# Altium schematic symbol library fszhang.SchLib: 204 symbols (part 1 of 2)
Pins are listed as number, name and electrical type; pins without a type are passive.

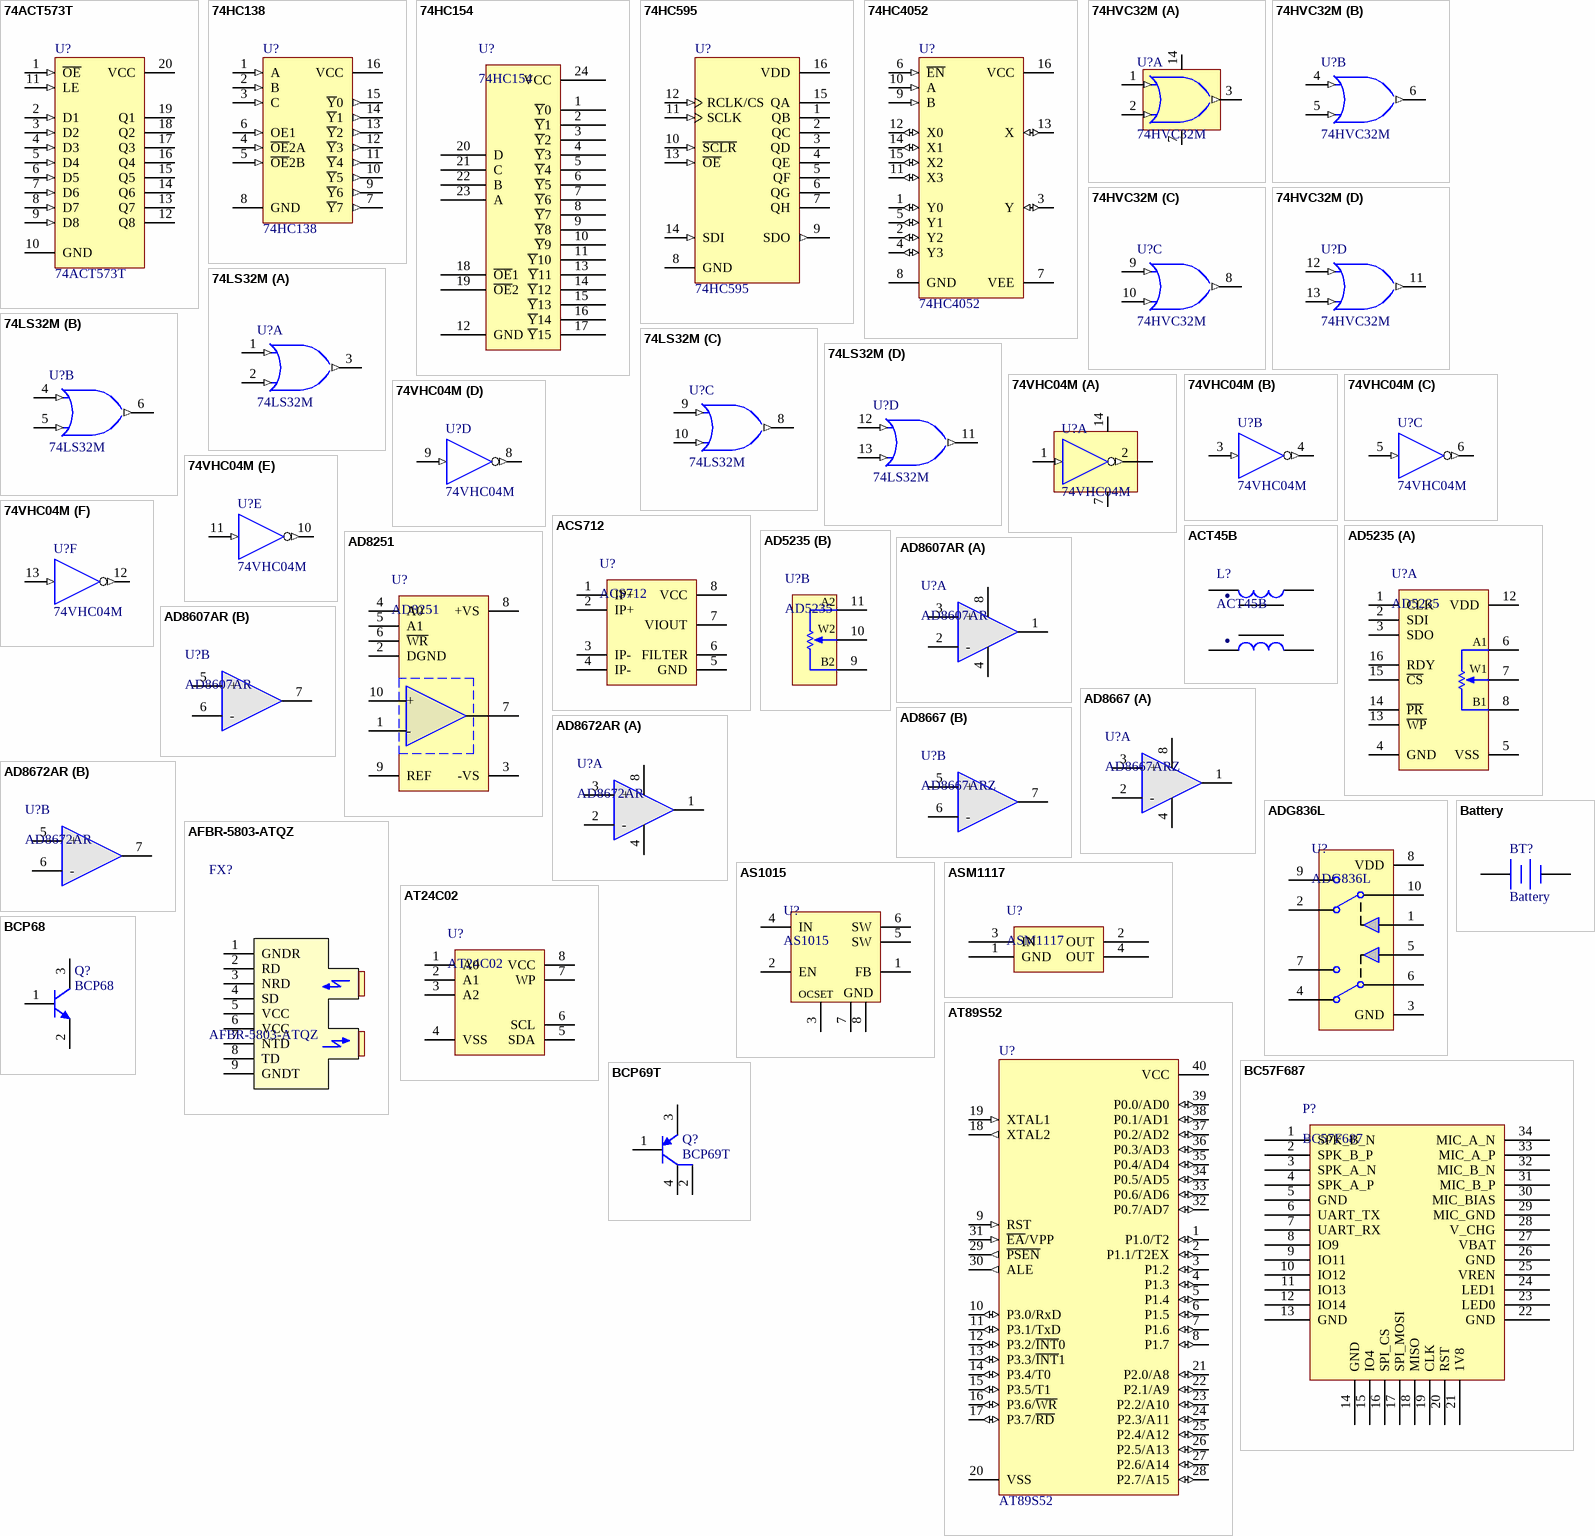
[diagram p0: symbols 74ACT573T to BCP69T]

## 74ACT573T
designator U?
双向数据传输
footprint TSSOP20 (Shrink Small Outline; 20 Leads; Body Width 4.4 mm; Pitch 0.65 mm)
footprint SO20_M (SOIC, 20-Leads, Body 12.8x7.5mm, Pitch 1.27mm, IPC Low Density)
pins: 1 ~{OE} (in), 2 D1 (in), 3 D2 (in), 4 D3 (in), 5 D4 (in), 6 D5 (in), 7 D6 (in), 8 D7 (in), 9 D8 (in), 10 GND (power), 11 LE (in), 12 Q8 (hiz), 13 Q7 (hiz), 14 Q6 (hiz), 15 Q5 (hiz), 16 Q4 (hiz), 17 Q3 (hiz), 18 Q2 (hiz), 19 Q1 (hiz), 20 VCC (power)

## 74HC138
designator U?
138译码器
footprint NSO16_M (SOIC, 16-Leads, Body 9.9x3.9mm, Pitch 1.27mm, IPC Low Density)
footprint DIP16 (8列双排)
pins: 1 A (in), 2 B (in), 3 C (in), 4 ~{OE}2A (in), 5 ~{OE}2B (in), 6 OE1 (in), 7 ~{Y}7 (out), 8 GND (power), 9 ~{Y}6 (out), 10 ~{Y}5 (out), 11 ~{Y}4 (out), 12 ~{Y}3 (out), 13 ~{Y}2 (out), 14 ~{Y}1 (out), 15 ~{Y}0 (out), 16 VCC (power)

## 74HC154
designator U?
4-16译码器
footprint DW024_N (74hc154)
footprint DIP24 (DIP; 24,74ls154)
pins: 1 ~{Y}0 (power), 2 ~{Y}1 (power), 3 ~{Y}2 (power), 4 ~{Y}3 (power), 5 ~{Y}4 (power), 6 ~{Y}5 (power), 7 ~{Y}6 (power), 8 ~{Y}7 (power), 9 ~{Y}8 (power), 10 ~{Y}9 (power), 11 ~{Y}10 (power), 12 GND (power), 13 ~{Y}11 (power), 14 ~{Y}12 (power), 15 ~{Y}13 (power), 16 ~{Y}14 (power), 17 ~{Y}15 (power), 18 ~{OE}1 (power), 19 ~{OE}2 (power), 20 D (power), 21 C (power), 22 B (power), 23 A (power), 24 VCC (power)

## 74HC595
designator U?
移位寄存器; ComponentAvailability: Not for New Design
footprint DIP16 (8列双排)
footprint NSO16_M (SOIC, 16-Leads, Body 9.9x3.9mm, Pitch 1.27mm, IPC Low Density)
pins: 1 QB (hiz), 2 QC (hiz), 3 QD (hiz), 4 QE (hiz), 5 QF (hiz), 6 QG (hiz), 7 QH (hiz), 8 GND (power), 9 SDO (out), 10 ~{SCLR} (in), 11 SCLK (in), 12 RCLK/CS (in), 13 ~{OE} (in), 14 SDI (in), 15 QA (hiz), 16 VDD (power)

## 74HC4052
designator U?
双通道模拟开关
footprint NSO16_M (SOIC, 16-Leads, Body 9.9x3.9mm, Pitch 1.27mm, IPC Low Density)
footprint DIP16
pins: 1 Y0 (io), 2 Y2 (io), 3 Y (io), 4 Y3 (io), 5 Y1 (io), 6 ~{EN} (in), 7 VEE (power), 8 GND (power), 9 B (in), 10 A (in), 11 X3 (io), 12 X0 (io), 13 X (io), 14 X1 (io), 15 X2 (io), 16 VCC (power)

## 74HVC32M
designator U?
双输入或门
footprint SOP-14N (SOP, 14-Leads,)
part A pins: 1 A (in), 2 B (in), 3 Y (out), 7 GND (power), 14 VCC (power)
part B pins: 4 A (in), 5 B (in), 6 Y (out)
part C pins: 8 Y (out), 9 A (in), 10 B (in)
part D pins: 11 Y (out), 12 A (in), 13 B (in)

## 74LS32M
designator U?
双输入或门
footprint SOP-14N (SOP, 14-Leads,)
pins on every part: 7 GND (power) hidden to GND, 14 VCC (power) hidden to VCC
part A pins: 1 A (in), 2 B (in), 3 Y (out)
part B pins: 4 A (in), 5 B (in), 6 Y (out)
part C pins: 8 Y (out), 9 A (in), 10 B (in)
part D pins: 11 Y (out), 12 A (in), 13 B (in)

## 74VHC04M
designator U?
非门; IC_Technology: S
footprint SOP-14N (SOP, 14-Leads,)
part A pins: 1 A (in), 2 Y (out), 7 GND (power), 14 VCC (power)
part B pins: 3 A (in), 4 Y (out)
part C pins: 5 A (in), 6 Y (out)
part D pins: 8 Y (out), 9 A (in)
part E pins: 10 Y (out), 11 A (in)
part F pins: 12 Y (out), 13 A (in)

## ACS712
designator U?
电流检测芯片
footprint SOIC127P610X175-8N (ACS712)
pins: 1 IP+, 2 IP+, 3 IP-, 4 IP-, 5 GND, 6 FILTER, 7 VIOUT, 8 VCC

## ACT45B
designator L?
共模电感
footprint L-TDK
pins: 1, 2, 3, 4

## AD5235
designator U?
数控电阻
footprint TSSOP16_M (TSOP, 16-Leads, Body 5x4.4mm, Pitch 0.65mm, IPC Low Density)
part A pins: 1 CLK, 2 SDI, 3 SDO, 4 GND, 5 VSS, 6 A1, 7 W1, 8 B1, 12 VDD, 13 ~{WP}, 14 ~{PR}, 15 ~{CS}, 16 RDY
part B pins: 9 B2, 10 W2, 11 A2

## AD8251
designator U?
可控增益运放
footprint MSOP-UN10_N (TSSOP)
pins: 1 -, 2 DGND, 3 -VS, 4 A0, 5 A1, 6 ~{WR}, 7 OUT, 8 +VS, 9 REF, 10 +

## AD8607AR
designator U?
双运放
footprint NSO8_N (SOIC-max660)
part A pins: 1 OUT1, 2 -, 3 +, 4 V- (power), 8 V+ (power)
part B pins: 5 +, 6 -, 7 OUT2

## AD8667
designator U?, comment AD8667ARZ
双运放
footprint NSO8_N (SOIC-max660)
part A pins: 1 OUT1, 2 -, 3 +, 4 V- (power), 8 V+ (power)
part B pins: 5 +, 6 -, 7 OUT2

## AD8672AR
designator U?
双运放
footprint NSO8_N (SOIC-max660)
part A pins: 1 OUT1, 2 -, 3 +, 4 V- (power), 8 V+ (power)
part B pins: 5 +, 6 -, 7 OUT2

## ADG836L
designator U?
双刀双掷数字开关
footprint MSOP-UN10_N (TSSOP)
pins: 1 IN1, 2 SA, 3 GND, 4 S2A, 5 IN2, 6 D2, 7 S2B, 8 VDD, 9 S1B, 10 D1

## AFBR-5803-ATQZ
designator FX?
光以太网
footprint AFBR-5803AQZ (光以太网)
pins: 1 GNDR, 2 RD, 3 NRD, 4 SD, 5 VCC, 6 VCC, 7 NTD, 8 TD, 9 GNDT

## AS1015
designator U?
可调升压芯片
footprint NSO8_N (SOIC-max660)
pins: 1 FB (power), 2 EN (power), 3 OCSET (power), 4 IN (power), 5 SW (power), 6 SW (power), 7 GND (power), 8 GND (power)

## ASM1117
designator U?
3.3V稳压芯片
footprint SOT-223 (ASM1117 -3.3V)
pins: 1 GND, 2 OUT, 3 IN, 4 OUT

## AT24C02
designator U?
EEROM存储器
footprint SOIC8_N (8-Pin Small Outline Integrated Circuit Package (SOIC8), IPC Medium Density)
pins: 1 A0, 2 A1, 3 A2, 4 VSS, 5 SDA, 6 SCL, 7 WP, 8 VCC

## AT89S52
designator U?
51系列单片机
footprint DIP-40 (51单片机)
pins: 1 P1.0/T2 (io), 2 P1.1/T2EX (io), 3 P1.2 (io), 4 P1.3 (io), 5 P1.4 (io), 6 P1.5 (io), 7 P1.6 (io), 8 P1.7 (io), 9 RST (in), 10 P3.0/RxD (io), 11 P3.1/TxD (io), 12 P3.2/~{INT}0 (io), 13 P3.3/~{INT}1 (io), 14 P3.4/T0 (io), 15 P3.5/T1 (io), 16 P3.6/~{WR} (io), 17 P3.7/~{RD} (io), 18 XTAL2 (out), 19 XTAL1 (in), 20 VSS (power), 21 P2.0/A8 (io), 22 P2.1/A9 (io), 23 P2.2/A10 (io), 24 P2.3/A11 (io), 25 P2.4/A12 (io), 26 P2.5/A13 (io), 27 P2.6/A14 (io), 28 P2.7/A15 (io), 29 ~{PSEN} (out), 30 ALE (out), 31 ~{EA}/VPP (in), 32 P0.7/AD7 (io), 33 P0.6/AD6 (io), 34 P0.5/AD5 (io), 35 P0.4/AD4 (io), 36 P0.3/AD3 (io), 37 P0.2/AD2 (io), 38 P0.1/AD1 (io), 39 P0.0/AD0 (io), 40 VCC (power)

## Battery
designator BT?
备份电池
footprint CR1220 (钮扣电池)
pins: 1 +, 2 -

## BC57F687
designator P?
蓝牙音频模块
footprint HDR34_BT (蓝牙模块)
pins: 1 SPK_B_N, 2 SPK_B_P, 3 SPK_A_N, 4 SPK_A_P, 5 GND, 6 UART_TX, 7 UART_RX, 8 IO9, 9 IO11, 10 IO12, 11 IO13, 12 IO14, 13 GND, 14 GND, 15 IO4, 16 SPI_CS, 17 SPI_MOSI, 18 MISO, 19 CLK, 20 RST, 21 1V8, 22 GND, 23 LED0, 24 LED1, 25 VREN, 26 GND, 27 VBAT, 28 V_CHG, 29 MIC_GND, 30 MIC_BIAS, 31 MIC_B_P, 32 MIC_B_N, 33 MIC_A_P, 34 MIC_A_N

## BCP68
designator Q?
NPN三极管
footprint SOT-23 (普通?)
pins: 1 B, 2 E, 3 C

## BCP69T
designator Q?
PNP三极管
footprint SOT-223 (ASM1117 -3.3V)
pins: 1 B, 2 C, 3 E, 4

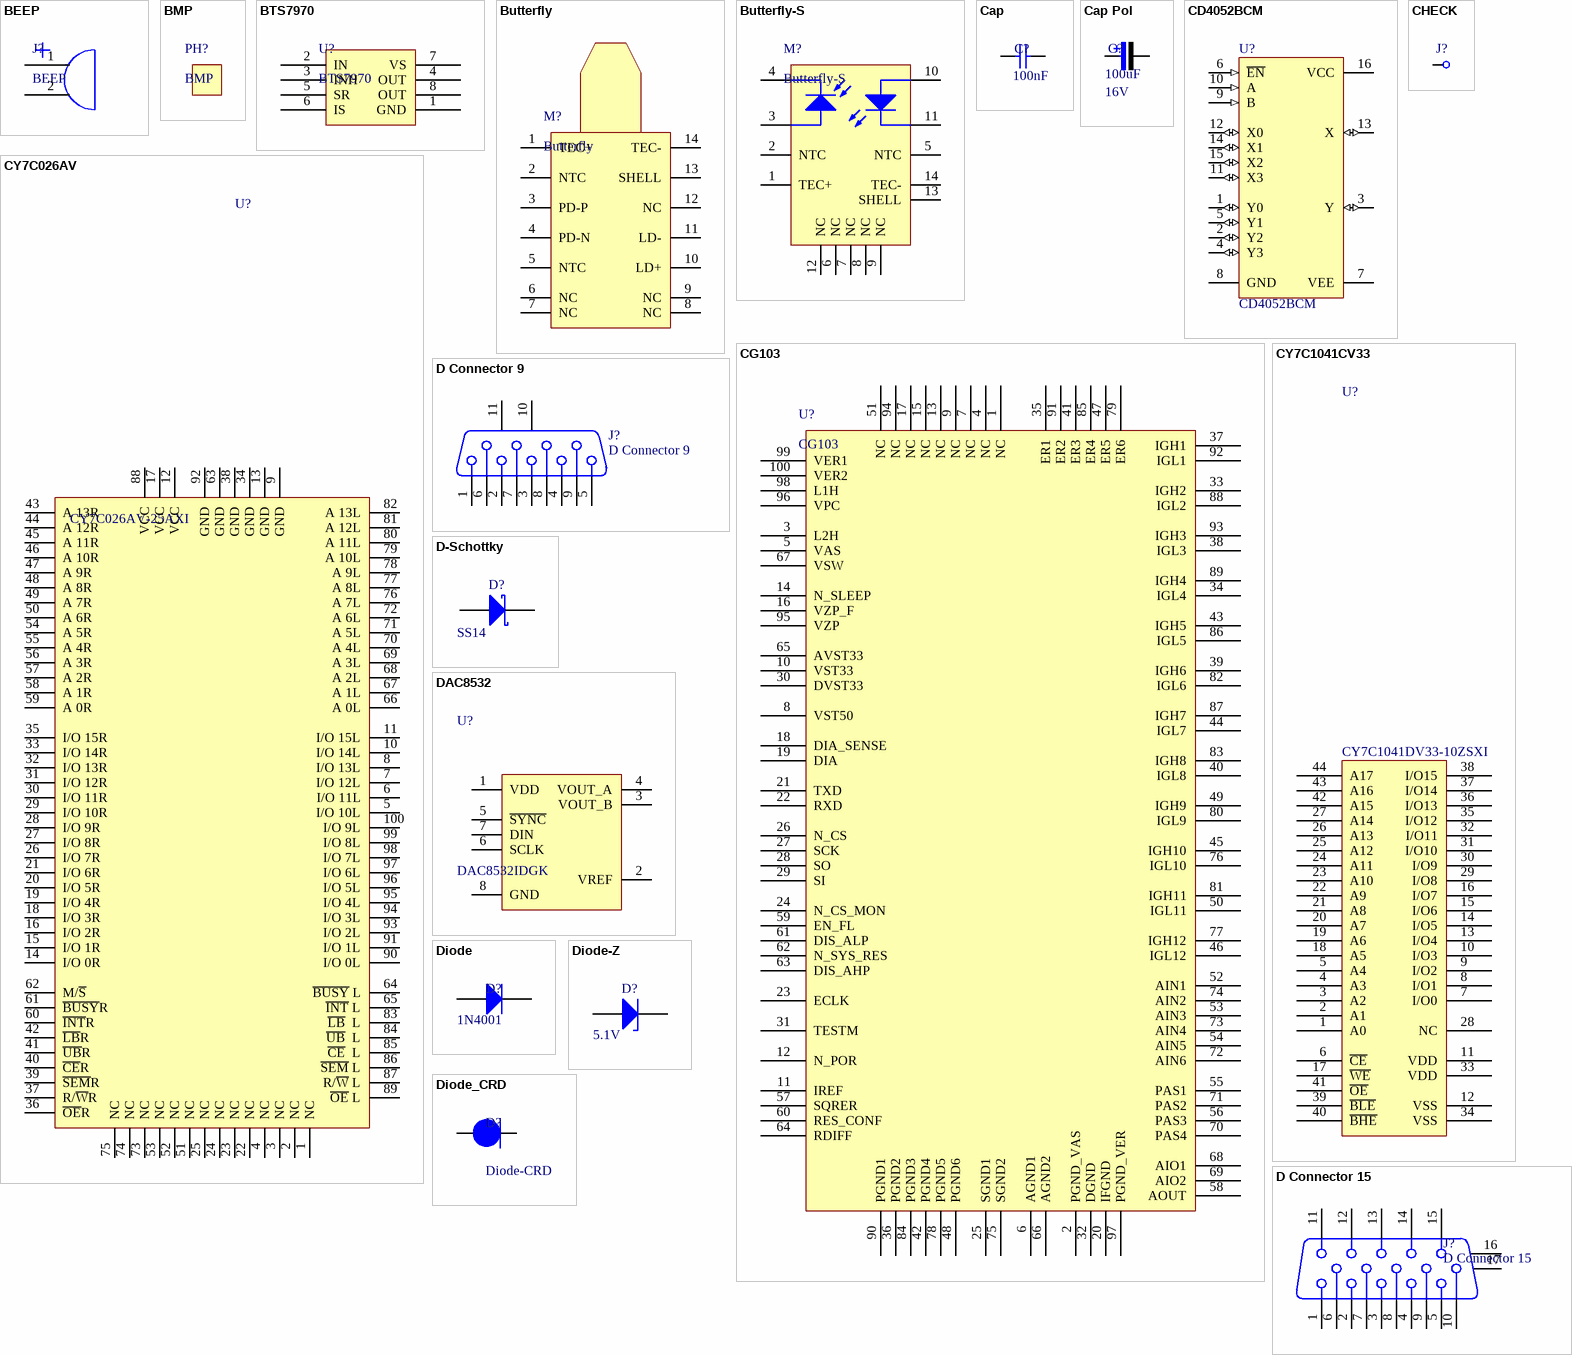
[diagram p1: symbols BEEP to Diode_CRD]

## BEEP
designator J?
蜂鸣器
footprint Beep (蜂鸣器)
pins: 1 0, 2 1

## BMP
designator PH?
闪电符号
footprint LOGO_Thunder
footprint LOGO-3S

## BTS7970
designator U?
电机驱动
footprint TO-263-7 (TO, 8-Pads,7970)
pins: 1 GND (power), 2 IN (power), 3 INH (power), 4 OUT (power), 5 SR (power), 6 IS (power), 7 VS (power), 8 OUT (power)

## Butterfly
designator M?
功率激光器
pins: 1 TEC+, 2 NTC, 3 PD-P, 4 PD-N, 5 NTC, 6 NC, 7 NC, 8 NC, 9 NC, 10 LD+, 11 LD-, 12 NC, 13 SHELL, 14 TEC-

## Butterfly-S
designator M?
功率激光器
pins: 1 TEC+, 2 NTC, 3 PD-P, 4 PD-N, 5 NTC, 6 NC, 7 NC, 8 NC, 9 NC, 10 LD+, 11 LD-, 12 NC, 13 SHELL, 14 TEC-

## Cap
designator C?  value 100nF  (hidden comment: Cap)
无极性电容
footprint C-RAD (瓷片电容)
footprint C-RAD-0805 (贴片电容)
footprint C-RAD-0603 (贴片电容)
footprint 0603-2 (贴片无丝印)
footprint 0805-2 (贴片无丝印)
footprint C-RAD-3528 (贴片电容)
pins: 1, 2

## Cap Pol
designator C?  value 100uF  Vol: 16V  (hidden comment: Cap Pol)
极性电解电容
footprint CAP-7343 (钽电容)
footprint CAP-3528 (钽电容)
footprint CAP-3216 (钽电容)
footprint C-RB-S10 (贴片电解)
footprint C-RB-S6 (贴片电解)
footprint CAP-6032 (钽电容)
footprint C-RB-10 (35V470uF电容)
footprint C-RB-18 (35V2200uF电容)
footprint C-RB-8 (35V 220UF电容)
footprint C-RB-12 (35V470uF电容)
footprint C-RB-S8 (贴片电解)
pins: 1, 2
1 alternate drawing of the same symbol

## CD4052BCM
designator U?
双通道模拟开关
footprint NSO16_M (SOIC, 16-Leads, Body 9.9x3.9mm, Pitch 1.27mm, IPC Low Density)
pins: 1 Y0 (io), 2 Y2 (io), 3 Y (io), 4 Y3 (io), 5 Y1 (io), 6 ~{EN} (in), 7 VEE (power), 8 GND (power), 9 B (in), 10 A (in), 11 X3 (io), 12 X0 (io), 13 X (io), 14 X1 (io), 15 X2 (io), 16 VCC (power)

## CG103
designator U?
BOSCH点火芯片
footprint LQFP-100_M (Thin QFP, 100)
pins: 1 NC, 2 PGND_VAS, 3 L2H, 4 NC, 5 VAS, 6 AGND1, 7 NC, 8 VST50, 9 NC, 10 VST33, 11 IREF, 12 N_POR, 13 NC, 14 N_SLEEP, 15 NC, 16 VZP_F, 17 NC, 18 DIA_SENSE, 19 DIA, 20 IFGND, 21 TXD, 22 RXD, 23 ECLK, 24 N_CS_MON, 25 SGND1, 26 N_CS, 27 SCK, 28 SO, 29 SI, 30 DVST33, 31 TESTM, 32 DGND, 33 IGH2, 34 IGL4, 35 ER1, 36 PGND2, 37 IGH1, 38 IGL3, 39 IGH6, 40 IGL8, 41 ER3, 42 PGND4, 43 IGH5, 44 IGL7, 45 IGH10, 46 IGL12, 47 ER5, 48 PGND6, 49 IGH9, 50 IGL11, 51 NC, 52 AIN1, 53 AIN3, 54 AIN5, 55 PAS1, 56 PAS3, 57 SQRER, 58 AOUT, 59 EN_FL, 60 RES_CONF, 61 DIS_ALP, 62 N_SYS_RES, 63 DIS_AHP, 64 RDIFF, 65 AVST33, 66 AGND2, 67 VSW, 68 AIO1, 69 AIO2, 70 PAS4, 71 PAS2, 72 AIN6, 73 AIN4, 74 AIN2, 75 SGND2, 76 IGL10, 77 IGH12, 78 PGND5, 79 ER6, 80 IGL9, 81 IGH11, 82 IGL6, 83 IGH8, 84 PGND3, 85 ER4, 86 IGL5, 87 IGH7, 88 IGL2, 89 IGH4, 90 PGND1, 91 ER2, 92 IGL1, 93 IGH3, 94 NC, 95 VZP, 96 VPC, 97 PGND_VER, 98 L1H, 99 VER1, 100 VER2

## CHECK
designator J?  (value not drawn)
测试点
footprint CHECK-A (Connector; Plug)
footprint CHECK-B (Connector; Plug)
pins: 1

## CY7C026AV
designator U?, comment CY7C026AV-25AXI
RAM
footprint TQFP100_M (Thin QFP, 100-Leads, Body 14x14mm, Pitch 0.5mm, IPC Low Density)
pins: 1 NC, 2 NC, 3 NC, 4 NC, 5 I/O 10L, 6 I/O 11L, 7 I/O 12L, 8 I/O 13L, 9 GND, 10 I/O 14L, 11 I/O 15L, 12 VCC, 13 GND, 14 I/O 0R, 15 I/O 1R, 16 I/O 2R, 17 VCC, 18 I/O 3R, 19 I/O 4R, 20 I/O 5R, 21 I/O 6R, 22 NC, 23 NC, 24 NC, 25 NC, 26 I/O 7R, 27 I/O 8R, 28 I/O 9R, 29 I/O 10R, 30 I/O 11R, 31 I/O 12R, 32 I/O 13R, 33 I/O 14R, 34 GND, 35 I/O 15R, 36 ~{OE}R, 37 R/~{W}R, 38 GND, 39 ~{SEM}R, 40 ~{CE}R, 41 ~{UB}R, 42 ~{LB}R, 43 A 13R, 44 A 12R, 45 A 11R, 46 A 10R, 47 A 9R, 48 A 8R, 49 A 7R, 50 A 6R, 51 NC, 52 NC, 53 NC, 54 A 5R, 55 A 4R, 56 A 3R, 57 A 2R, 58 A 1R, 59 A 0R, 60 ~{INT}R, 61 ~{BUSY}R, 62 M/~{S}, 63 GND, 64 ~{BUSY} L, 65 ~{INT} L, 66 A 0L, 67 A 1L, 68 A 2L, 69 A 3L, 70 A 4L, 71 A 5L, 72 A 6L, 73 NC, 74 NC, 75 NC, 76 A 7L, 77 A 8L, 78 A 9L, 79 A 10L, 80 A 11L, 81 A 12L, 82 A 13L, 83 ~{LB}  L, 84 ~{UB}  L, 85 ~{CE}  L, 86 ~{SEM} L, 87 R/~{W} L, 88 VCC, 89 ~{OE} L, 90 I/O 0L, 91 I/O 1L, 92 GND, 93 I/O 2L, 94 I/O 3L, 95 I/O 4L, 96 I/O 5L, 97 I/O 6L, 98 I/O 7L, 99 I/O 8L, 100 I/O 9L

## CY7C1041CV33
designator U?, comment CY7C1041DV33-10ZSXI
RAM
footprint TSOP-44N (TSOP, 44-Leads, Body 18.2x10.0mm (max), Pitch 0.80mm, IPC Medium Density)
pins: 1 A0, 2 A1, 3 A2, 4 A3, 5 A4, 6 ~{CE}, 7 I/O0, 8 I/O1, 9 I/O2, 10 I/O3, 11 VDD, 12 VSS, 13 I/O4, 14 I/O5, 15 I/O6, 16 I/O7, 17 ~{WE}, 18 A5, 19 A6, 20 A7, 21 A8, 22 A9, 23 A10, 24 A11, 25 A12, 26 A13, 27 A14, 28 NC, 29 I/O8, 30 I/O9, 31 I/O10, 32 I/O11, 33 VDD, 34 VSS, 35 I/O12, 36 I/O13, 37 I/O14, 38 I/O15, 39 ~{BLE}, 40 ~{BHE}, 41 ~{OE}, 42 A15, 43 A16, 44 A17

## D Connector 9
designator J?
串口; PackageDocument: O; Positions: 9; Gender: Receptacle
footprint DB9-M (DB9公座)
footprint DB9-F (DB9母座)
pins: 1, 2, 3, 4, 5, 6, 7, 8, 9, 10 MH1, 11 MH2

## D Connector 15
designator J?
VGA; PackageDocument: O; Positions: 9; Gender: Receptacle
footprint DB15-M (VGA公)
footprint DB15-F (VGAĸ)
pins: 1, 2, 3, 4, 5, 6, 7, 8, 9, 10, 11, 12, 13, 14, 15, 16 MH2, 17 MH1

## D-Schottky
designator D?  Type: SS14  (hidden comment: D-Schottky)
肖特基二极管
footprint DIODE-SMA (贴片二极管)
footprint DIODE-SMC (SS34贴片肖特基二极管)
footprint DIODE-SMB (DO-214-AA/SMB; 2 C-Bend Leads; Body 5.3 x 3.6 mm, inc. leads (LxW))
pins: 1 A, 2 K

## DAC8532
designator U?, comment DAC8532IDGK
数模转换
footprint TSSOP-8
pins: 1 VDD (power), 2 VREF, 3 VOUT_B, 4 VOUT_A, 5 ~{SYNC}, 6 SCLK, 7 DIN, 8 GND

## Diode
designator D?  Type: 1N4001  (hidden comment: Diode)
二极管
footprint DIODE-AXL (直插二极管)
footprint DIODE-1206 (玻璃封装二极管)
footprint DIODE-SMA (贴片二)
pins: 1 A, 2 K

## Diode-Z
designator D?  value 5.1V  (hidden comment: Diode-Z)
稳压二极管
footprint DIODE-AXL (直插二极管)
footprint DIODE-1206 (玻璃封装二极管)
pins: 1 A, 2 K

## Diode_CRD
designator D?, comment Diode-CRD
恒流二极管
footprint DIODE-AXL (直插二极管)
footprint DIODE-1206 (玻璃封装二极管)
footprint DIODE-SMA (贴片二)
pins: 1 A, 2 K

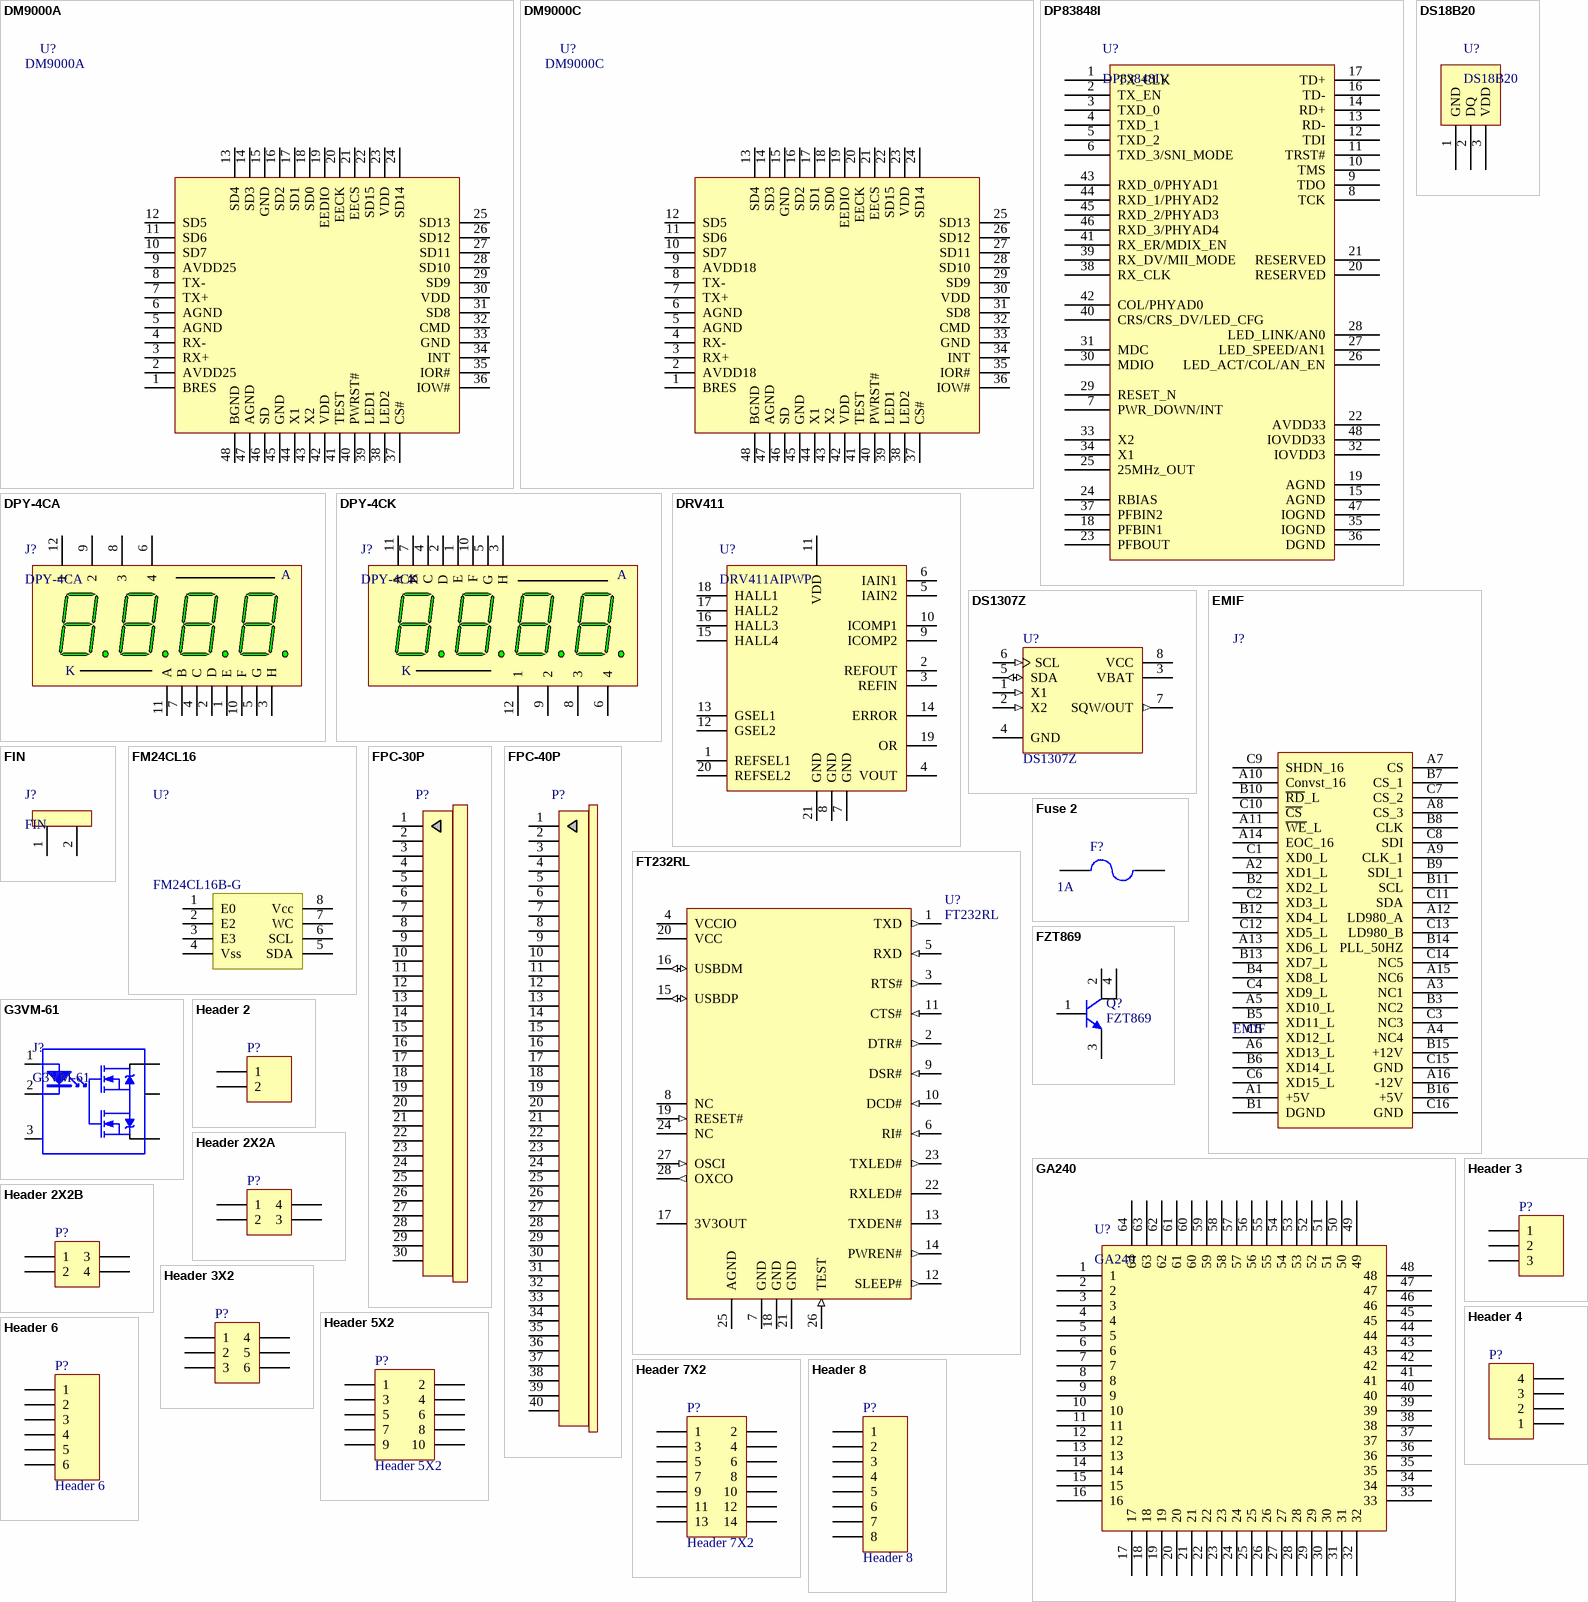
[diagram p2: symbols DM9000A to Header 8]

## DM9000A
designator U?
网络芯片
footprint LQFP-48_M (Thin QFP, 48-Leads, Body 7x7mm, Pitch 0.5mm, IPC Low Density)
pins: 1 BRES, 2 AVDD25, 3 RX+, 4 RX-, 5 AGND, 6 AGND, 7 TX+, 8 TX-, 9 AVDD25, 10 SD7, 11 SD6, 12 SD5, 13 SD4, 14 SD3, 15 GND, 16 SD2, 17 SD1, 18 SD0, 19 EEDIO, 20 EECK, 21 EECS, 22 SD15, 23 VDD, 24 SD14, 25 SD13, 26 SD12, 27 SD11, 28 SD10, 29 SD9, 30 VDD, 31 SD8, 32 CMD, 33 GND, 34 INT, 35 IOR#, 36 IOW#, 37 CS#, 38 LED2, 39 LED1, 40 PWRST#, 41 TEST, 42 VDD, 43 X2, 44 X1, 45 GND, 46 SD, 47 AGND, 48 BGND

## DM9000C
designator U?
网络芯片
footprint LQFP-48_M (Thin QFP, 48-Leads, Body 7x7mm, Pitch 0.5mm, IPC Low Density)
pins: 1 BRES, 2 AVDD18, 3 RX+, 4 RX-, 5 AGND, 6 AGND, 7 TX+, 8 TX-, 9 AVDD18, 10 SD7, 11 SD6, 12 SD5, 13 SD4, 14 SD3, 15 GND, 16 SD2, 17 SD1, 18 SD0, 19 EEDIO, 20 EECK, 21 EECS, 22 SD15, 23 VDD, 24 SD14, 25 SD13, 26 SD12, 27 SD11, 28 SD10, 29 SD9, 30 VDD, 31 SD8, 32 CMD, 33 GND, 34 INT, 35 IOR#, 36 IOW#, 37 CS#, 38 LED2, 39 LED1, 40 PWRST#, 41 TEST, 42 VDD, 43 X2, 44 X1, 45 GND, 46 SD, 47 AGND, 48 BGND

## DP83848I
designator U?, comment DP83848IV
网络芯片
footprint TQFP48_N (Thin QFP, 48-Leads, Body 7x7mm, Pitch 0.5mm, IPC Medium Density)
pins: 1 TX_CLK, 2 TX_EN, 3 TXD_0, 4 TXD_1, 5 TXD_2, 6 TXD_3/SNI_MODE, 7 PWR_DOWN/INT, 8 TCK, 9 TDO, 10 TMS, 11 TRST#, 12 TDI, 13 RD-, 14 RD+, 15 AGND, 16 TD-, 17 TD+, 18 PFBIN1, 19 AGND, 20 RESERVED, 21 RESERVED, 22 AVDD33, 23 PFBOUT, 24 RBIAS, 25 25MHz_OUT, 26 LED_ACT/COL/AN_EN, 27 LED_SPEED/AN1, 28 LED_LINK/AN0, 29 RESET_N, 30 MDIO, 31 MDC, 32 IOVDD3, 33 X2, 34 X1, 35 IOGND, 36 DGND, 37 PFBIN2, 38 RX_CLK, 39 RX_DV/MII_MODE, 40 CRS/CRS_DV/LED_CFG, 41 RX_ER/MDIX_EN, 42 COL/PHYAD0, 43 RXD_0/PHYAD1, 44 RXD_1/PHYAD2, 45 RXD_2/PHYAD3, 46 RXD_3/PHYAD4, 47 IOGND, 48 IOVDD33

## DPY-4CA
designator J?
共阳4位数码管
footprint DYP-4BIT (数码管)
pins: 1 E "Anode", 2 D "Anode", 3 H "Anode", 4 C "Anode", 5 G "Anode", 6 4 "Cathode", 7 B "Anode", 8 3 "Anode", 9 2 "Anode", 10 F "Anode", 11 A "Anode", 12 1 "Cathode"

## DPY-4CK
designator J?
共阴4位数码管
footprint DYP-4BIT (数码管)
pins: 1 E "Anode", 2 D "Anode", 3 H "Anode", 4 C "Anode", 5 G "Anode", 6 4 "Cathode", 7 B "Anode", 8 3 "Anode", 9 2 "Anode", 10 F "Anode", 11 A "Anode", 12 1 "Cathode"

## DRV411
designator U?, comment DRV411AIPWP
闭环磁电流
footprint TSSOP20P_M (TSOP, 20-Leads, Body 6.5x4.4mm, Pitch 0.65mm, IPC Low Density)
pins: 1 REFSEL1, 2 REFOUT, 3 REFIN, 4 VOUT, 5 IAIN2, 6 IAIN1, 7 GND, 8 GND, 9 ICOMP2, 10 ICOMP1, 11 VDD, 12 GSEL2, 13 GSEL1, 14 ERROR, 15 HALL4, 16 HALL3, 17 HALL2, 18 HALL1, 19 OR, 20 REFSEL2, 21 GND

## DS18B20
designator U?
温度传感器
footprint TO-92A (直插三极管)
pins: 1 GND, 2 DQ, 3 VDD

## DS1307Z
designator U?
实时时钟
footprint SOIC8_N (8-Pin Small Outline Integrated Circuit Package (SOIC8), IPC Medium Density)
pins: 1 X1 (in), 2 X2 (in), 3 VBAT (power), 4 GND (power), 5 SDA (io), 6 SCL (in), 7 SQW/OUT (out), 8 VCC (power)

## EMIF
designator J?
接插件
footprint HDR16X3_HA
footprint HDR16X3_HB
pins: A1 +5V, A2 XD1_L, A3 NC1, A4 NC4, A5 XD10_L, A6 XD13_L, A7 CS, A8 CS_3, A9 CLK_1, A10 Convst_16, A11 ~{WE}_L, A12 LD980_A, A13 XD6_L, A14 EOC_16, A15 NC6, A16 -12V, B1 DGND, B2 XD2_L, B3 NC2, B4 XD8_L, B5 XD11_L, B6 XD14_L, B7 CS_1, B8 CLK, B9 SDI_1, B10 ~{RD}_L, B11 SCL, B12 XD4_L, B13 XD7_L, B14 PLL_50HZ, B15 +12V, B16 +5V, C1 XD0_L, C2 XD3_L, C3 NC3, C4 XD9_L, C5 XD12_L, C6 XD15_L, C7 CS_2, C8 SDI, C9 SHDN_16, C10 ~{CS}, C11 SDA, C12 XD5_L, C13 LD980_B, C14 NC5, C15 GND, C16 GND

## FIN
designator J?
散热片
footprint FIN-P2
pins: 1, 2

## FM24CL16
designator U?, comment FM24CL16B-G
铁电存储器
footprint NSO8_N (SOIC-max660)
pins: 1 E0, 2 E2, 3 E3, 4 Vss, 5 SDA, 6 SCL, 7 WC, 8 Vcc

## FPC-30P
designator P?, comment FPC  (value not drawn)
FPC排线连接器
footprint FPC0.8-30P-A (FPC)
pins: 1, 2, 3, 4, 5, 6, 7, 8, 9, 10, 11, 12, 13, 14, 15, 16, 17, 18, 19, 20, 21, 22, 23, 24, 25, 26, 27, 28, 29, 30

## FPC-40P
designator P?, comment FPC  (value not drawn)
FPC排线连接器
footprint FPC0.5-40P-A
pins: 1, 2, 3, 4, 5, 6, 7, 8, 9, 10, 11, 12, 13, 14, 15, 16, 17, 18, 19, 20, 21, 22, 23, 24, 25, 26, 27, 28, 29, 30, 31, 32, 33, 34, 35, 36, 37, 38, 39, 40

## FT232RL
designator U?
USB转串口
footprint SSOP-28 (FT232)
pins: 1 TXD (out), 2 DTR# (out), 3 RTS# (out), 4 VCCIO (power), 5 RXD (in), 6 RI# (in), 7 GND (power), 8 NC, 9 DSR# (in), 10 DCD# (in), 11 CTS# (in), 12 SLEEP# (out), 13 TXDEN# (oc), 14 PWREN# (out), 15 USBDP (io), 16 USBDM (io), 17 3V3OUT (power), 18 GND (power), 19 RESET# (in), 20 VCC (power), 21 GND (power), 22 RXLED# (oc), 23 TXLED# (out), 24 NC, 25 AGND (power), 26 TEST (in), 27 OSCI (in), 28 OXCO (out)

## Fuse 2
designator F?, comment value 1A  (hidden comment: Fuse)
保险丝
footprint 1812 (3.5A保险丝)
pins: 1, 2

## FZT869
designator Q?
NPN三极管
footprint SOT-223 (ASM1117 -3.3V)
pins: 1 B, 2 C, 3 E, 4 C

## G3VM-61
designator J?
半导体继电器
footprint SOT254P-6 (继电器)
pins: 1 A "Anode", 2 K "Cathode", 3, 4, 5, 6

## GA240
designator U?
Freescale16位单片机
footprint LQFP-64 (LQFP64)
pins: 1, 2, 3, 4, 5, 6, 7, 8, 9, 10, 11, 12, 13, 14, 15, 16, 17, 18, 19, 20, 21, 22, 23, 24, 25, 26, 27, 28, 29, 30, 31, 32, 33, 34, 35, 36, 37, 38, 39, 40, 41, 42, 43, 44, 45, 46, 47, 48, 49, 50, 51, 52, 53, 54, 55, 56, 57, 58, 59, 60, 61, 62, 63, 64

## Header 2
designator P?  (value not drawn)
接插件
footprint HDR2X1_C (3.81接插件)
footprint HDR2X1_D1 (5.08mm端)
footprint HDR2X1_A (Connector; Header; 2 Position)
footprint HDR2X1_B2 (Connector; Header; 4 Position)
footprint HDR2X1_B1 (Connector; Header; 4 Position)
footprint HDR2X1_D2 (Connector; Header; 4 Position)
pins: 1, 2

## Header 2X2A
designator P?  (value not drawn)
接插件
footprint HDR2X2_A (Connector; Header; 2 Position)
pins: 1, 2, 3, 4

## Header 2X2B
designator P?  (value not drawn)
接插件
footprint HDR2X2_B (Connector; Header; 2 Position)
pins: 1, 2, 3, 4

## Header 3
designator P?  (value not drawn)
接插件
footprint HDR3X1_B1 (Connector; Header; 3 Position)
footprint HDR3X1_A (Connector; Header; 3 Position)
footprint HDR3X1_C (3.81MM接插件)
footprint HDR3X1_D1 (5.08mm端子)
footprint HDR3X1_D2 (5.08mm端子)
footprint HDR3X1_B2 (Connector; Header; 3 Position)
footprint HDR3X1_B4 (Connector; Header; 4 Position)
pins: 1, 2, 3

## Header 3X2
designator P?  (value not drawn)
接插件
footprint HDR3X2_A2_2.0
pins: 1, 2, 3, 4, 5, 6

## Header 4
designator P?  (value not drawn)
接插件
footprint HDR4X1_A (Connector; Header; 4 Position)
footprint HDR4X1_B1 (Connector; Header; 4 Position)
footprint HDR4X1_B2 (Connector; Header; 4 Position)
footprint HDR4X1_F
footprint HDR4X1_C (3.81MM接插件)
pins: 1, 2, 3, 4

## Header 5X2
designator P?
接插件
footprint HDR5X2_A3
footprint HDR5X2_A1 (Connector; Header; 5x2 Position)
footprint HDR5X2_B1_2.0
footprint HDR5X2_C2
pins: 1, 2, 3, 4, 5, 6, 7, 8, 9, 10

## Header 6
designator P?
接插件
footprint HDR6X1_B2 (Connector; Header; 3 Position)
footprint HDR6X1_B1 (Connector; Header; 4 Position)
footprint HDR6X1_A (Connector; Header; 4 Position)
pins: 1, 2, 3, 4, 5, 6

## Header 7X2
designator P?
Header, 7-Pin
footprint HDR7X2_A1 (Connector; Header; 7x2 Position)
footprint HDR7X2_B1 (Connector)
footprint HDR7X2_B1_2.0
pins: 1, 2, 3, 4, 5, 6, 7, 8, 9, 10, 11, 12, 13, 14

## Header 8
designator P?
Header, 8-Pin
footprint PH2.0-8P
pins: 1, 2, 3, 4, 5, 6, 7, 8

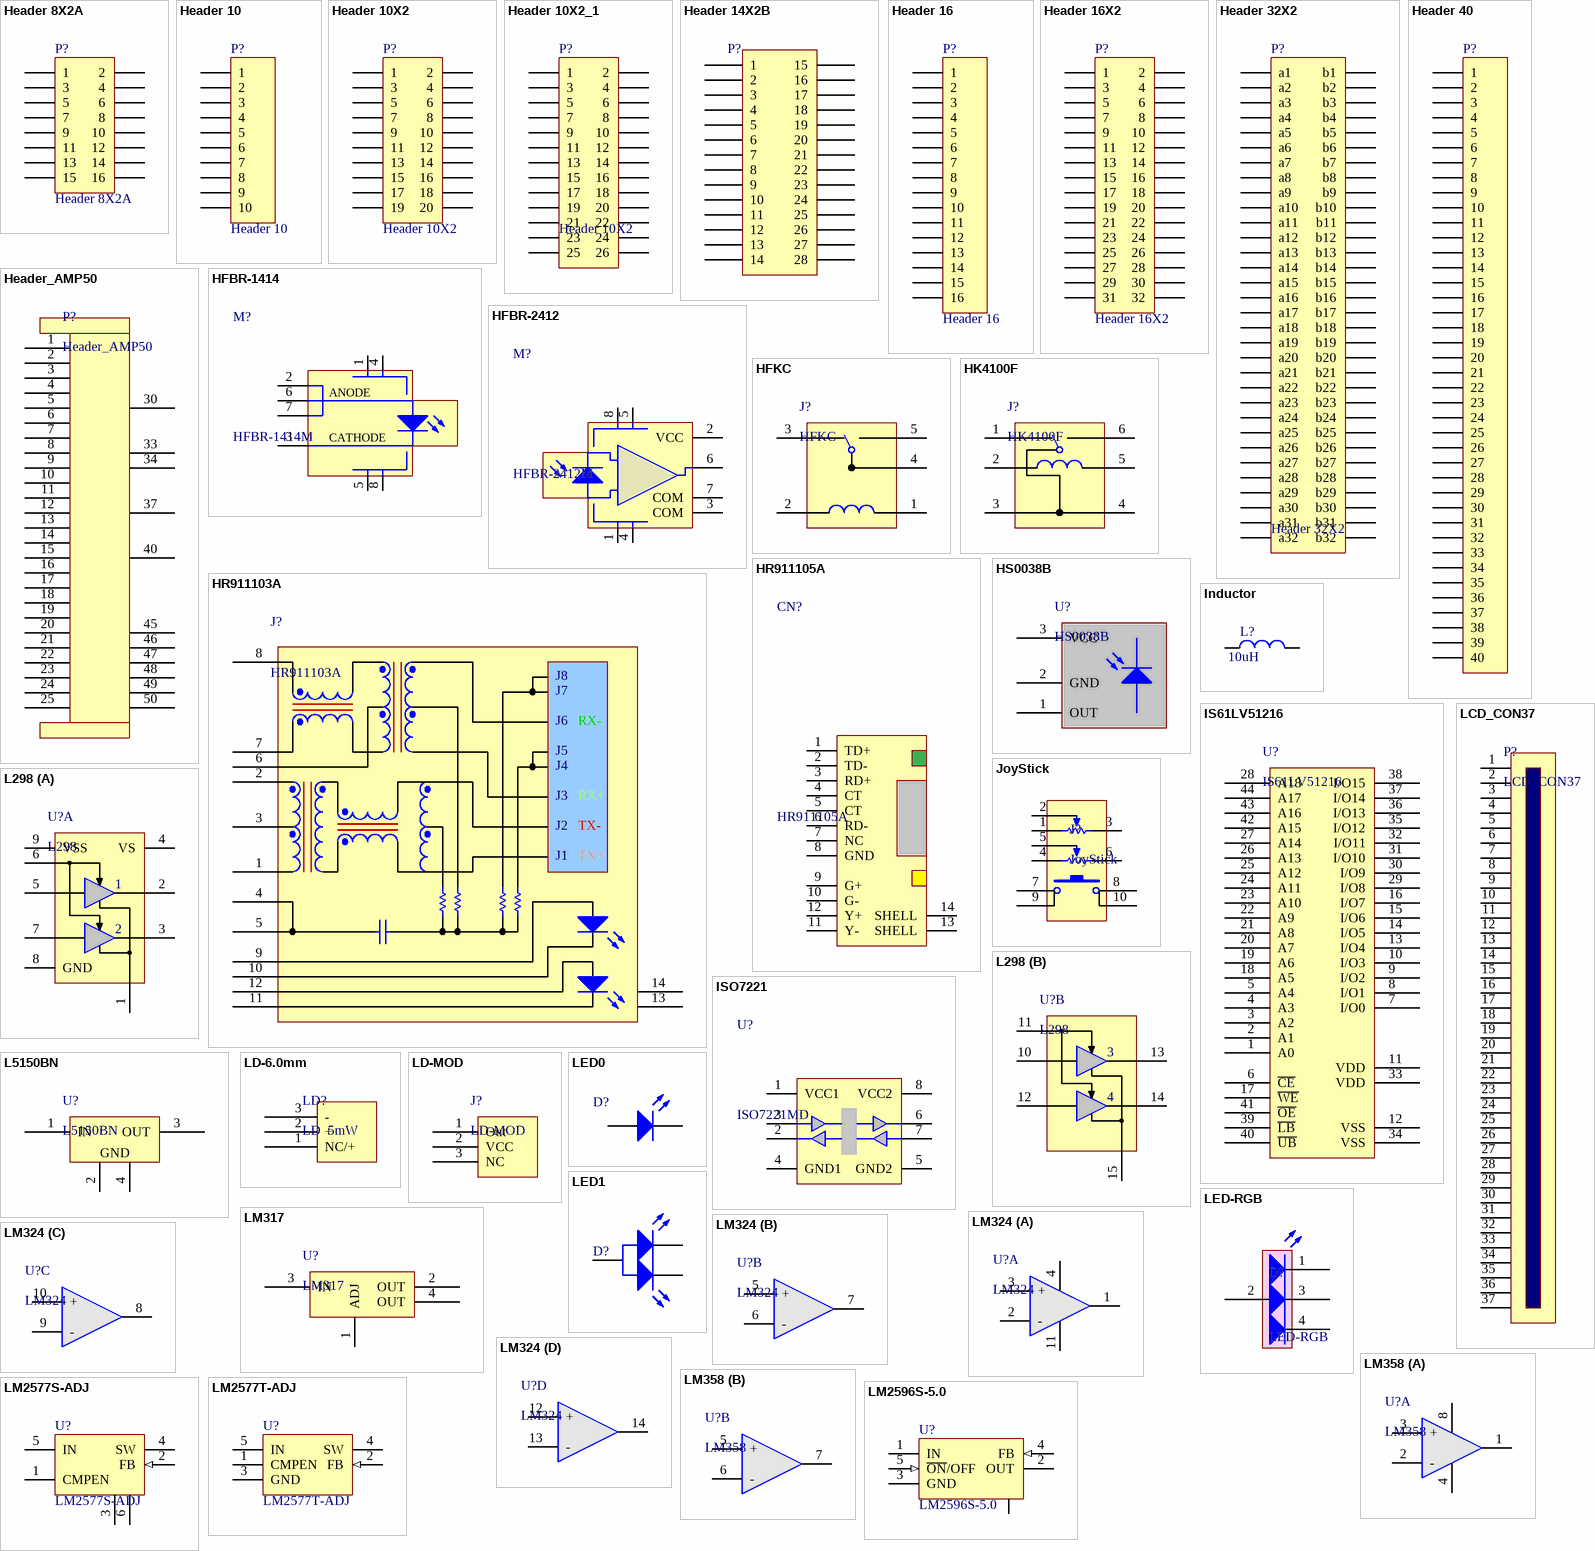
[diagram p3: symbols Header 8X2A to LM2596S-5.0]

## Header 8X2A
designator P?
接插件
footprint HDR8X2_A1 (Connector; Header; 8x2 Position)
footprint HDR8X2_E1
pins: 1, 2, 3, 4, 5, 6, 7, 8, 9, 10, 11, 12, 13, 14, 15, 16

## Header 10
designator P?
Header, 10-Pin
footprint PH2.0-10P
pins: 1, 2, 3, 4, 5, 6, 7, 8, 9, 10

## Header 10X2
designator P?
Header, 10-Pin
footprint HDR10X2_A1 (Connector; Header; 10x2 Position)
footprint HDR10X2_B1
footprint HDR10X2_B1_2.0
pins: 1, 2, 3, 4, 5, 6, 7, 8, 9, 10, 11, 12, 13, 14, 15, 16, 17, 18, 19, 20

## Header 10X2_1
designator P?, comment Header 10X2
Header, 10-Pin
pins: 1, 2, 3, 4, 5, 6, 7, 8, 9, 10, 11, 12, 13, 14, 15, 16, 17, 18, 19, 20, 21, 22, 23, 24, 25, 26

## Header 14X2B
designator P?  (value not drawn)
2*14双排插针
footprint HDR14X2_A2
pins: 1 (power), 2 (power), 3 (power), 4 (power), 5 (power), 6 (power), 7 (power), 8 (power), 9 (power), 10 (power), 11 (power), 12 (power), 13 (power), 14 (power), 15 (power), 16 (power), 17 (power), 18 (power), 19 (power), 20 (power), 21 (power), 22 (power), 23 (power), 24 (power), 25 (power), 26 (power), 27 (power), 28 (power)

## Header 16
designator P?
Header16贴片
footprint HDR16X1_A (Connector; Header; 16 Position)
footprint FPC1.0-16P-A (FPC)
pins: 1, 2, 3, 4, 5, 6, 7, 8, 9, 10, 11, 12, 13, 14, 15, 16

## Header 16X2
designator P?
接插件
footprint HDR16X2 (Connector; Header; 16x2 Position)
footprint HDR16X2-HB
pins: 1, 2, 3, 4, 5, 6, 7, 8, 9, 10, 11, 12, 13, 14, 15, 16, 17, 18, 19, 20, 21, 22, 23, 24, 25, 26, 27, 28, 29, 30, 31, 32

## Header 32X2
designator P?
接插件
footprint HDR32X2_HA (Connector; Header; 30x2 Position)
footprint HDR32X2_HB (Connector; Header; 30x2 Position)
pins: a1, a2, a3, a4, a5, a6, a7, a8, a9, a10, a11, a12, a13, a14, a15, a16, a17, a18, a19, a20, a21, a22, a23, a24, a25, a26, a27, a28, a29, a30, a31, a32, b1, b2, b3, b4, b5, b6, b7, b8, b9, b10, b11, b12, b13, b14, b15, b16, b17, b18, b19, b20, b21, b22, b23, b24, b25, b26, b27, b28, b29, b30, b31, b32

## Header 40
designator P?  (value not drawn)
接插件
footprint HDR40X1_A (Connector; Header; 30 Position)
pins: 1, 2, 3, 4, 5, 6, 7, 8, 9, 10, 11, 12, 13, 14, 15, 16, 17, 18, 19, 20, 21, 22, 23, 24, 25, 26, 27, 28, 29, 30, 31, 32, 33, 34, 35, 36, 37, 38, 39, 40

## Header_AMP50
designator P?
控制器接插件
footprint HDR25X2_H (控制器接插件)
pins: 1, 2, 3, 4, 5, 6, 7, 8, 9, 10, 11, 12, 13, 14, 15, 16, 17, 18, 19, 20, 21, 22, 23, 24, 25, 30, 33, 34, 37, 40, 45, 46, 47, 48, 49, 50

## HFBR-1414
designator M?, comment HFBR-1414M
光发送
footprint HFBR-X41XMZ
pins: 1 NC, 2 ANODE, 3 CATHODE, 4 NC, 5 NC, 6 ANODE, 7 ANODE, 8 NC

## HFBR-2412
designator M?, comment HFBR-2412M
光接收
footprint HFBR-X41XMZ
pins: 1 NC, 2 VCC, 3 COM, 4 NC, 5 NC, 6 DATA, 7 COM, 8 NC

## HFKC
designator J?
单刀双掷继电器
footprint HFKC (继电器)
pins: 1, 2, 3, 4, 5

## HK4100F
designator J?
单刀双掷继电器
footprint HK4100F (继电器)
pins: 1, 2, 3, 4, 5, 6

## HR911103A
designator J?
网络接口; PackageDocument: 1988
footprint RJ8-HR911103A (网线接口)
pins: 1 TD+, 2 TD-, 3 TD-, 4 TD-, 5 GND, 6 GND, 7 RD+, 8 RD-, 9 GLED+, 10 GLED-, 11 YLED-, 12 YLED+, 13, 14

## HR911105A
designator CN?
以太网接口
footprint RJ8-HR911105B
footprint RJ8-HR911105A
pins: 1 TD+, 2 TD-, 3 RD+, 4 CT, 5 CT, 6 RD-, 7 NC, 8 GND, 9 G+, 10 G-, 11 Y-, 12 Y+, 13 SHELL, 14 SHELL

## HS0038B
designator U?
红外接收器
footprint HS0038B (红外接收头)
pins: 1 OUT, 2 GND, 3 VCC

## Inductor
designator L?  value 10uH  (hidden comment: Inductor)
电感; Code_IEC: 1005
footprint L-SMD-7 (贴片电感7*7)
footprint L-RB-8 (Inductor)
footprint 1206 (10UH贴片电感)
footprint 0805-1 (贴片带丝印)
footprint L-RB-8F (ֱ?)
footprint L-SMD-10 (贴片电感10*10)
footprint L-SMD-12 (贴片电感12*12)
footprint 0805-2 (贴片无丝印)
pins: 1, 2

## IS61LV51216
designator U?
静态RAM
footprint TSOP-44N (TSOP, 44-Leads, Body 18.2x10.0mm (max), Pitch 0.80mm, IPC Medium Density)
pins: 1 A0, 2 A1, 3 A2, 4 A3, 5 A4, 6 ~{CE}, 7 I/O0, 8 I/O1, 9 I/O2, 10 I/O3, 11 VDD, 12 VSS, 13 I/O4, 14 I/O5, 15 I/O6, 16 I/O7, 17 ~{WE}, 18 A5, 19 A6, 20 A7, 21 A8, 22 A9, 23 A10, 24 A11, 25 A12, 26 A13, 27 A14, 28 A18, 29 I/O8, 30 I/O9, 31 I/O10, 32 I/O11, 33 VDD, 34 VSS, 35 I/O12, 36 I/O13, 37 I/O14, 38 I/O15, 39 ~{LB}, 40 ~{UB}, 41 ~{OE}, 42 A15, 43 A16, 44 A17

## ISO7221
designator U?, comment ISO7221MD
隔离芯片
footprint NSO8_N (SOIC-max660)
pins: 1 VCC1, 2 OutA, 3 B, 4 GND1, 5 GND2, 6 OutB, 7 InA, 8 VCC2

## JoyStick
designator J?
模拟摇杆
footprint JoyStick (模拟摇杆)
pins: 1 BOT, 2 TAP, 3 TOP, 4 BOT, 5 TAP, 6 TOP, 7, 8, 9, 10

## L298
designator U?
ST双电桥
footprint Multiwatt15-V
part A pins: 1 SENSEA, 2 OUT1, 3 OUT2, 4 VS, 5 IN1, 6 ENA, 7 IN2, 8 GND, 9 VSS
part B pins: 10 IN3, 11 ENB, 12 IN4, 13 OUT3, 14 OUT4, 15 SENSEB

## L5150BN
designator U?
5V稳压芯片
footprint SOT-223 (ASM1117 -3.3V)
pins: 1 IN, 2 GND, 3 OUT, 4 GND

## LCD_CON37
designator P?
LCD接口
footprint HDR37X1_F
pins: 1, 2, 3, 4, 5, 6, 7, 8, 9, 10, 11, 12, 13, 14, 15, 16, 17, 18, 19, 20, 21, 22, 23, 24, 25, 26, 27, 28, 29, 30, 31, 32, 33, 34, 35, 36, 37

## LD-6.0mm
designator LD?, comment LD  5mW
5MW激光
footprint LD-6.0 (激光直径6.0mm)
pins: 1 NC/+ (power), 2 + (power), 3 - (power)

## LD-MOD
designator J?
激光调制管
footprint LD-MOD (激光调制管)
pins: 1 Out (power), 2 VCC (power), 3 NC (power)

## LED0
designator D?  (value not drawn)
发光二极管
footprint LED_A1 (直径3MM发?)
footprint LED_0805 (贴片二?)
footprint LED_A2 (直径3MM?)
footprint LED-3528 (贴片二极管)
footprint LED_0603 (贴片无丝印)
pins: 1 A, 2 K

## LED1
designator D?  (value not drawn)
˫ɫLED
footprint LED_A3 (直径3MM二极管)
pins: 1 K1, 2 A, 3 K2

## LED-RGB
designator D?
三基色LED
footprint LED-RGB
pins: 1 R, 2 A, 3 G, 4 B

## LM317
designator U?
稳压芯片
footprint SOT-223 (ASM1117 -3.3V)
pins: 1 ADJ, 2 OUT, 3 IN, 4 OUT

## LM324
designator U?
4运放SOP8芯片
footprint SOP-14N (SOP, 14-Leads,)
part A pins: 1 OUT, 2 -, 3 +, 4 V+, 11 V-
part B pins: 5 +, 6 -, 7 OUT
part C pins: 8 OUT, 9 -, 10 +
part D pins: 12 +, 13 -, 14 OUT

## LM358
designator U?
双运放
footprint NSO8_N (SOIC-max660)
part A pins: 1 OUT1, 2 -, 3 +, 4 V- (power), 8 V+ (power)
part B pins: 5 +, 6 -, 7 OUT2

## LM2577S-ADJ
designator U?
DC升压; Note: Tab is connected to GND
footprint TO-263-5 (贴片LM2596)
pins: 1 CMPEN, 2 FB (in), 3 GND (power), 4 SW (power), 5 IN (power), 6

## LM2577T-ADJ
designator U?
DC升压; Note: Tab is connected to GND
footprint T05A (TO, Thru-Hole, Vertical, Heatsink Mounted; 5 In-Line Leads; Pitch 1.70 mm)
footprint T05D
pins: 1 CMPEN, 2 FB (in), 3 GND (power), 4 SW (power), 5 IN (power)

## LM2596S-5.0
designator U?
5V稳压芯片; Note: Tab is connected to GND
footprint TO-263-5 (贴片LM2596)
pins: 1 IN (power), 2 OUT (power), 3 GND (power), 4 FB (in), 5 ~{ON}/OFF (in), 6 (power)

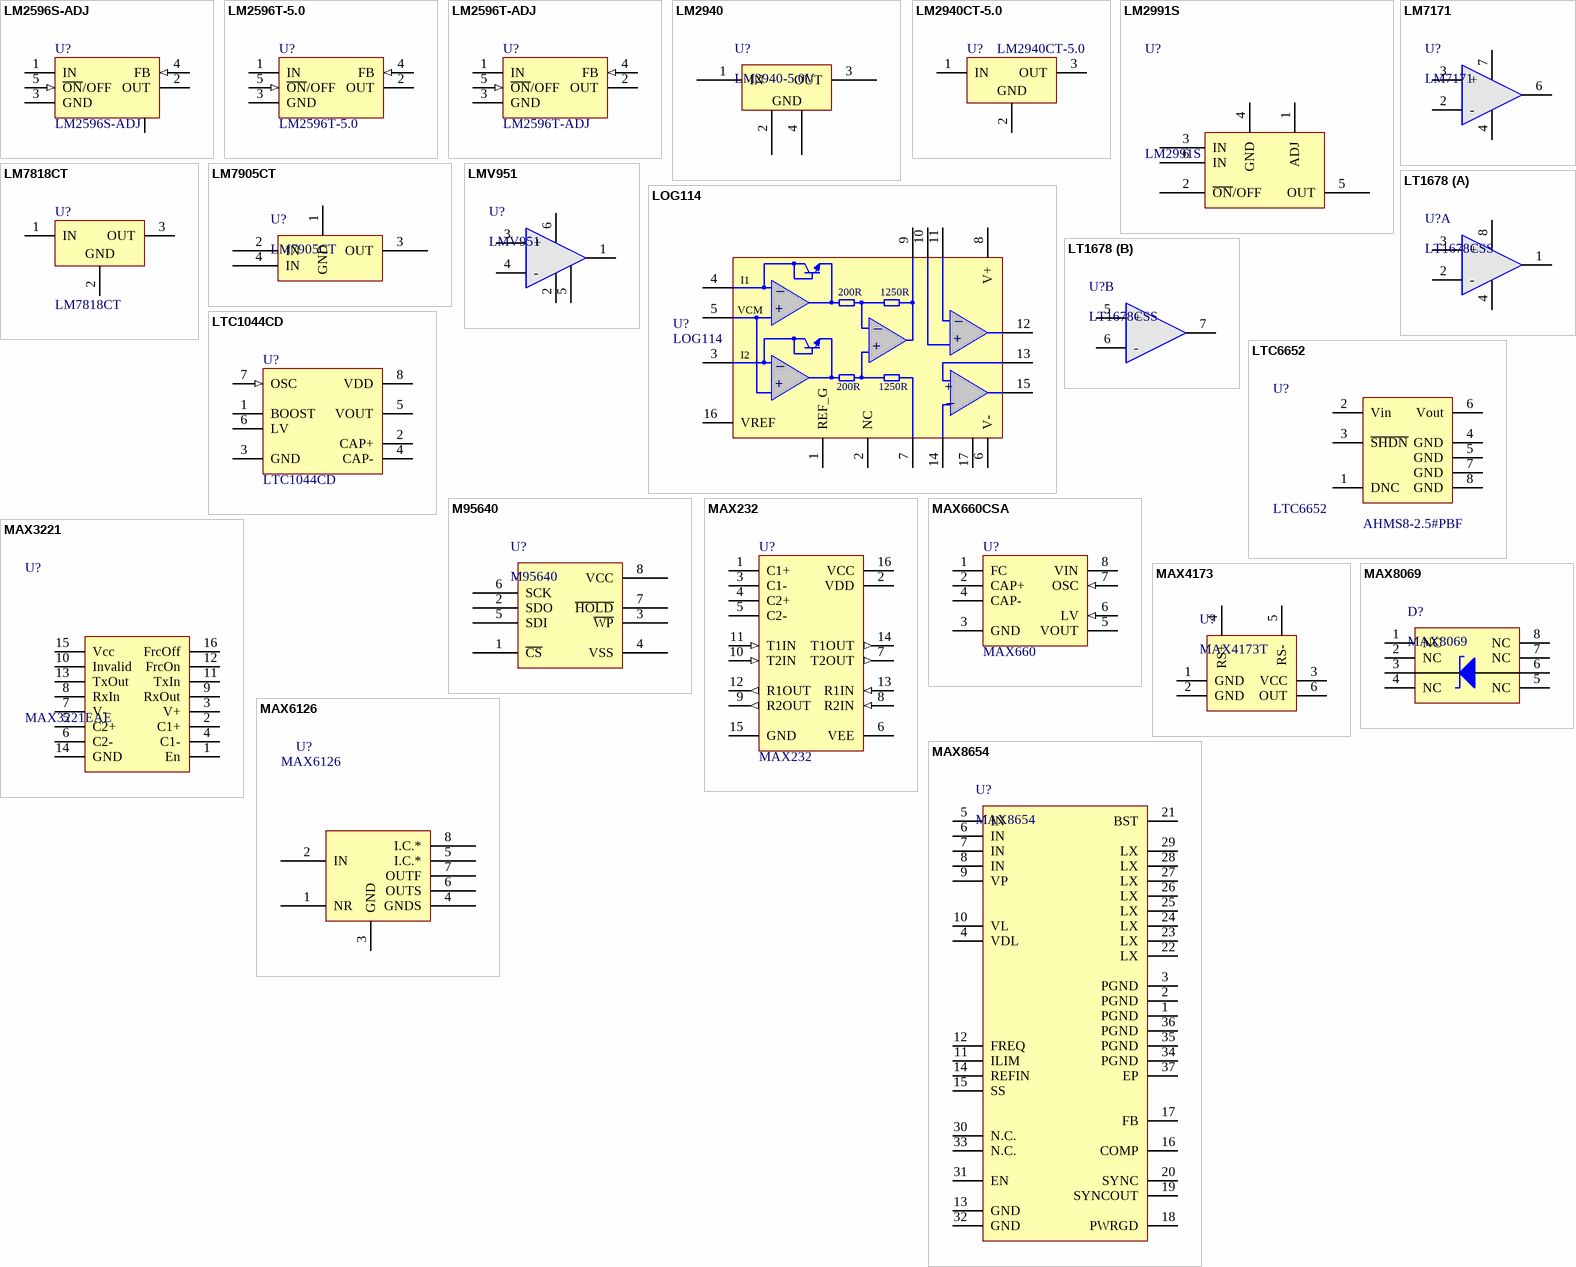
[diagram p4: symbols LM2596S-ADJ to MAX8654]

## LM2596S-ADJ
designator U?
可调稳压芯片; Note: Tab is connected to GND
footprint TO-263-5 (贴片LM2596)
pins: 1 IN (power), 2 OUT (power), 3 GND (power), 4 FB (in), 5 ~{ON}/OFF (in), 6 (power)

## LM2596T-5.0
designator U?
5V稳压芯片; Note: Tab is connected to GND
footprint T05A (TO, Thru-Hole, Vertical, Heatsink Mounted; 5 In-Line Leads; Pitch 1.70 mm)
footprint T05D
pins: 1 IN (power), 2 OUT (power), 3 GND (power), 4 FB (in), 5 ~{ON}/OFF (in)

## LM2596T-ADJ
designator U?
可调稳压芯片; Note: Tab is connected to GND
footprint T05A (TO, Thru-Hole, Vertical, Heatsink Mounted; 5 In-Line Leads; Pitch 1.70 mm)
footprint T05D
pins: 1 IN (power), 2 OUT (power), 3 GND (power), 4 FB (in), 5 ~{ON}/OFF (in)

## LM2940
designator U?, comment LM2940-5.0V
5V稳压芯片
footprint TO-263-3 (LM2940/LM1086)
pins: 1 IN (power), 2 GND (power), 3 OUT (power), 4 GND (power)

## LM2940CT-5.0
designator U?
1A 5V; Note: Tab is connected to GND
footprint T03B (TO, Thru-Hole, Vertical, Heatsink Mounted; 3 In-Line Leads; Pitch 2.54 mm)
pins: 1 IN (power), 2 GND (power), 3 OUT (power)

## LM2991S
designator U?
稳压芯片
footprint TO-263-5 (贴片LM2596)
pins: 1 ADJ, 2 ~{ON}/OFF, 3 IN, 4 GND, 5 OUT, 6 IN

## LM7171
designator U?
单运放
footprint NSO8_N (SOIC-max660)
pins: 2 -, 3 +, 4 V- (power), 6 OUT1, 7 V+ (power)

## LM7818CT
designator U?
Series 3-Terminal Positive Regulator; Note: Tab is connected to GND; ComponentAvailability: Obsolete
footprint T03B (TO, Thru-Hole, Vertical, Heatsink Mounted; 3 In-Line Leads; Pitch 2.54 mm)
pins: 1 IN (power), 2 GND (power), 3 OUT (power)

## LM7905CT
designator U?
稳压芯片
footprint SOT-223 (ASM1117 -3.3V)
footprint TO-263-3 (LM2940/LM1086)
pins: 1 GND, 2 IN, 3 OUT, 4 IN

## LMV951
designator U?
超低功耗运放
footprint SOT23-6 (Max4173)
pins: 1 OUT1, 2 V- (power), 3 +, 4 -, 5 S (power), 6 V+ (power)

## LOG114
designator U?
光电检测
footprint QFN-16 (QFN)
pins: 1 REF_G, 2 NC, 3 I2, 4 I1, 5 Vcmin, 6 V-, 7 CON, 8 V+, 9 VlogOUT, 10 +IN4, 11 -IN4, 12 VO4, 13 +IN5, 14 -IN5, 15 VO5, 16 VREF, 17 PAD

## LT1678
designator U?, comment LT1678CSS
双运放
footprint NSO8_N (SOIC-max660)
part A pins: 1 OUT1, 2 -, 3 +, 4 V- (power), 8 V+ (power)
part B pins: 5 +, 6 -, 7 OUT2

## LTC1044CD
designator U?
Switched-Capacitor Voltage Converter
footprint SOIC8_N (8-Pin Small Outline Integrated Circuit Package (SOIC8), IPC Medium Density)
pins: 1 BOOST, 2 CAP+, 3 GND (power), 4 CAP-, 5 VOUT (power), 6 LV, 7 OSC (in), 8 VDD (power)

## LTC6652
designator U?  Type: AHMS8-2.5#PBF
电压基准
footprint MSOP-MS8_M (TSOP, 8-Leads, Body 3x3mm, Pitch 0.65mm, IPC Low Density)
pins: 1 DNC, 2 Vin, 3 ~{SHDN}, 4 GND, 5 GND, 6 Vout, 7 GND, 8 GND
2 alternate drawings of the same symbol

## M95640
designator U?
footprint NSO8_N (SOIC-max660)
pins: 1 ~{CS}, 2 SDO, 3 ~{WP}, 4 VSS, 5 SDI, 6 SCK, 7 ~{HOLD}, 8 VCC

## MAX232
designator U?
+5V Powered, Multi-Channel RS-232 Driver/Receiver
footprint NSO16_M (SOIC, 16-Leads, Body 9.9x3.9mm, Pitch 1.27mm, IPC Low Density)
pins: 1 C1+, 2 VDD (power), 3 C1-, 4 C2+, 5 C2-, 6 VEE (power), 7 T2OUT (out), 8 R2IN (in), 9 R2OUT (out), 10 T2IN (in), 11 T1IN (in), 12 R1OUT (out), 13 R1IN (in), 14 T1OUT (out), 15 GND (power), 16 VCC (power)

## MAX660CSA
designator U?, comment MAX660
-5V电源芯片
footprint NSO8_N (SOIC-max660)
pins: 1 FC, 2 CAP+, 3 GND (power), 4 CAP-, 5 VOUT (power), 6 LV (in), 7 OSC (in), 8 VIN (power)

## MAX3221
designator U?, comment MAX3221EAE
串口电平转换
footprint TSSOP16_M (TSOP, 16-Leads, Body 5x4.4mm, Pitch 0.65mm, IPC Low Density)
pins: 1 En, 2 C1+, 3 V+, 4 C1-, 5 C2+, 6 C2-, 7 V-, 8 RxIn, 9 RxOut, 10 Invalid, 11 TxIn, 12 FrcOn, 13 TxOut, 14 GND, 15 Vcc, 16 FrcOff

## MAX4173
designator U?, comment MAX4173T
高端电流检测
footprint SOT23-6 (Max4173)
pins: 1 GND, 2 GND, 3 VCC, 4 RS+, 5 RS-, 6 OUT

## MAX6126
designator U?
电压基准
footprint NSO8_N (SOIC-max660)
pins: 1 NR, 2 IN, 3 GND, 4 GNDS, 5 I.C.*, 6 OUTS, 7 OUTF, 8 I.C.*

## MAX8069
designator D?
1.2V稳压二极管
footprint SOIC8_N (8-Pin Small Outline Integrated Circuit Package (SOIC8), IPC Medium Density)
pins: 1 NC, 2 NC, 3 C, 4 NC, 5 NC, 6 A, 7 NC, 8 NC

## MAX8654
designator U?
footprint VFQN36_V (QFN, 36-Leads, Body 6x6mm, Pitch 0.5mm, ST Recommended)
pins: 1 PGND, 2 PGND, 3 PGND, 4 VDL, 5 IN, 6 IN, 7 IN, 8 IN, 9 VP, 10 VL, 11 ILIM, 12 FREQ, 13 GND, 14 REFIN, 15 SS, 16 COMP, 17 FB, 18 PWRGD, 19 SYNCOUT, 20 SYNC, 21 BST, 22 LX, 23 LX, 24 LX, 25 LX, 26 LX, 27 LX, 28 LX, 29 LX, 30 N.C., 31 EN, 32 GND, 33 N.C., 34 PGND, 35 PGND, 36 PGND, 37 EP

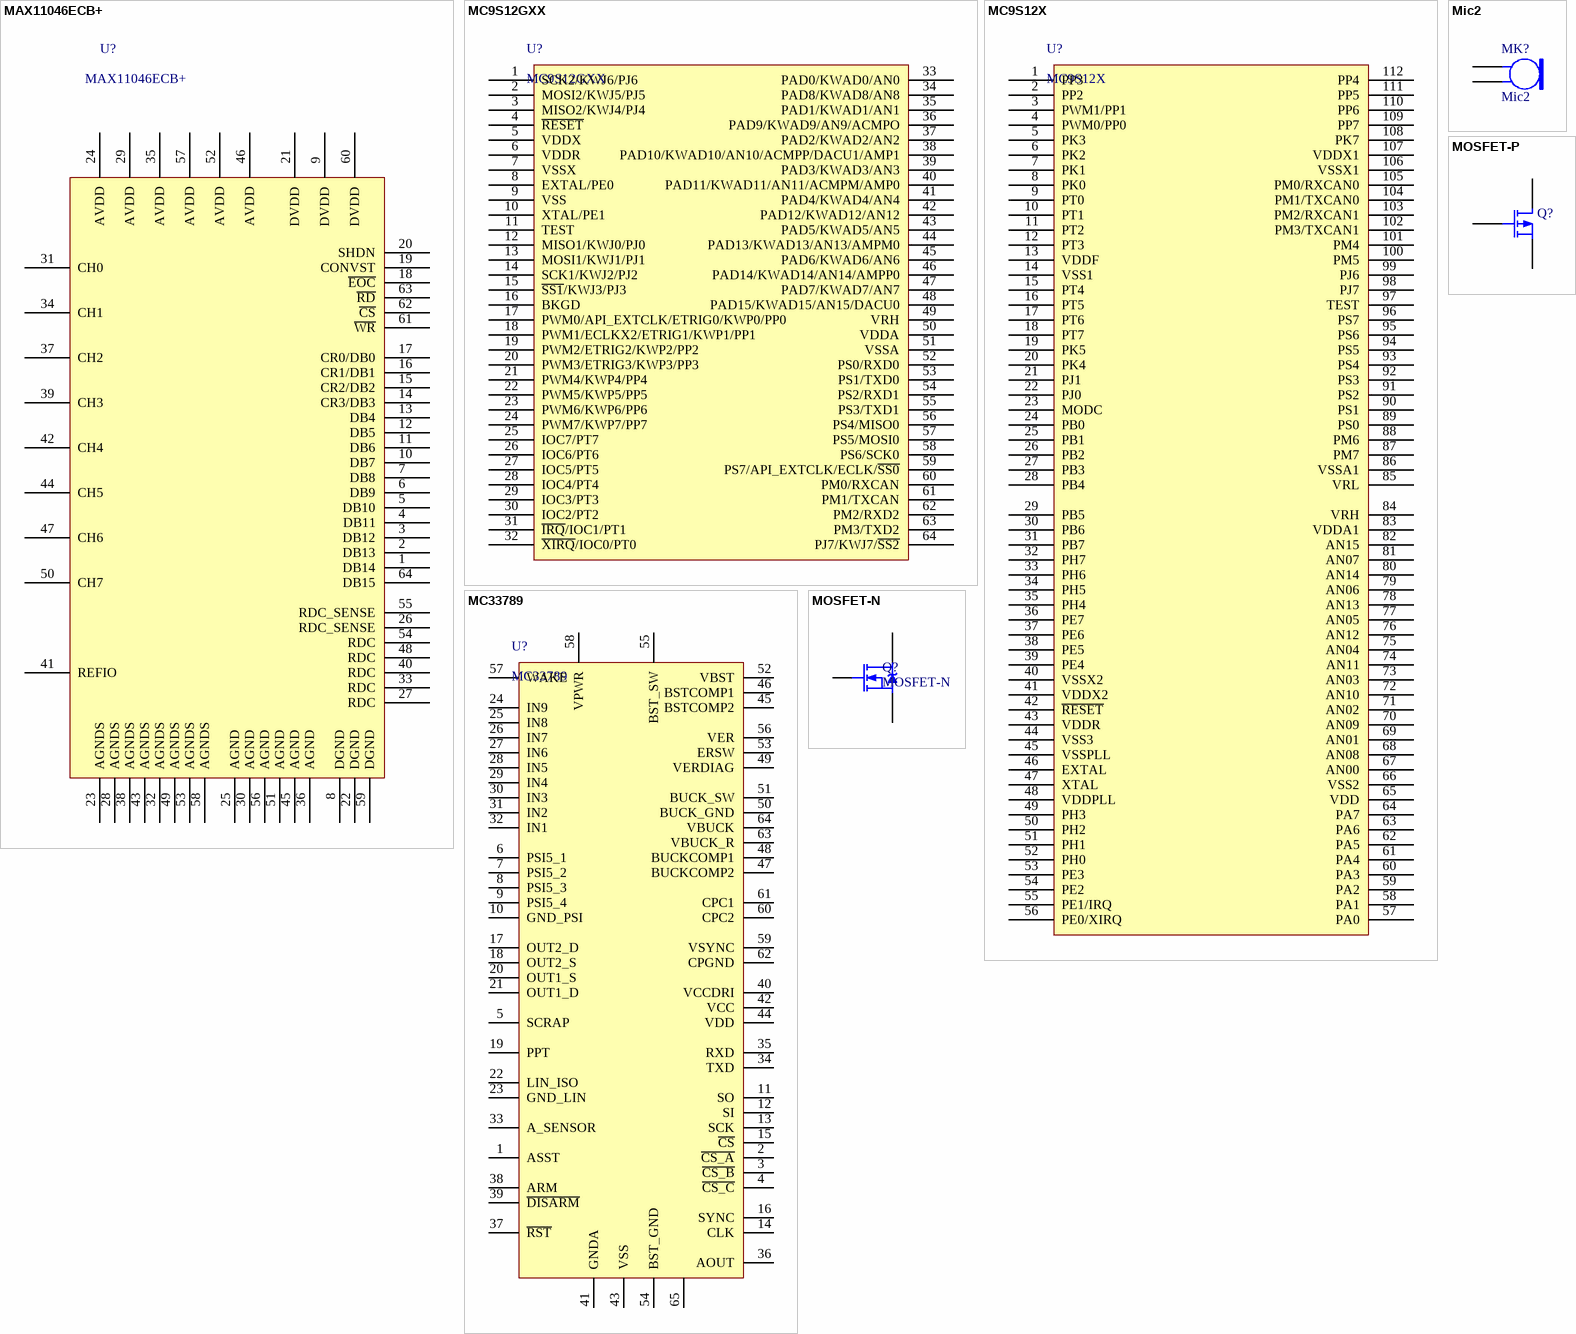
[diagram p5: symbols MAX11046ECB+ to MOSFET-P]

## MAX11046ECB+
designator U?
AD转换
footprint TQFP64_EP
pins: 1 DB14, 2 DB13, 3 DB12, 4 DB11, 5 DB10, 6 DB9, 7 DB8, 8 DGND, 9 DVDD, 10 DB7, 11 DB6, 12 DB5, 13 DB4, 14 CR3/DB3, 15 CR2/DB2, 16 CR1/DB1, 17 CR0/DB0, 18 ~{EOC}, 19 CONVST, 20 SHDN, 21 DVDD, 22 DGND, 23 AGNDS, 24 AVDD, 25 AGND, 26 RDC_SENSE, 27 RDC, 28 AGNDS, 29 AVDD, 30 AGND, 31 CH0, 32 AGNDS, 33 RDC, 34 CH1, 35 AVDD, 36 AGND, 37 CH2, 38 AGNDS, 39 CH3, 40 RDC, 41 REFIO, 42 CH4, 43 AGNDS, 44 CH5, 45 AGND, 46 AVDD, 47 CH6, 48 RDC, 49 AGNDS, 50 CH7, 51 AGND, 52 AVDD, 53 AGNDS, 54 RDC, 55 RDC_SENSE, 56 AGND, 57 AVDD, 58 AGNDS, 59 DGND, 60 DVDD, 61 ~{WR}, 62 ~{CS}, 63 ~{RD}, 64 DB15

## MC9S12GXX
designator U?
飞思卡尔单片机
footprint LQFP-64 (LQFP64)
pins: 1 SCK2/KWJ6/PJ6, 2 MOSI2/KWJ5/PJ5, 3 MISO2/KWJ4/PJ4, 4 ~{RESET}, 5 VDDX, 6 VDDR, 7 VSSX, 8 EXTAL/PE0, 9 VSS, 10 XTAL/PE1, 11 TEST, 12 MISO1/KWJ0/PJ0, 13 MOSI1/KWJ1/PJ1, 14 SCK1/KWJ2/PJ2, 15 ~{SS1}/KWJ3/PJ3, 16 BKGD, 17 PWM0/API_EXTCLK/ETRIG0/KWP0/PP0, 18 PWM1/ECLKX2/ETRIG1/KWP1/PP1, 19 PWM2/ETRIG2/KWP2/PP2, 20 PWM3/ETRIG3/KWP3/PP3, 21 PWM4/KWP4/PP4, 22 PWM5/KWP5/PP5, 23 PWM6/KWP6/PP6, 24 PWM7/KWP7/PP7, 25 IOC7/PT7, 26 IOC6/PT6, 27 IOC5/PT5, 28 IOC4/PT4, 29 IOC3/PT3, 30 IOC2/PT2, 31 ~{IRQ}/IOC1/PT1, 32 ~{XIRQ}/IOC0/PT0, 33 PAD0/KWAD0/AN0, 34 PAD8/KWAD8/AN8, 35 PAD1/KWAD1/AN1, 36 PAD9/KWAD9/AN9/ACMPO, 37 PAD2/KWAD2/AN2, 38 PAD10/KWAD10/AN10/ACMPP/DACU1/AMP1, 39 PAD3/KWAD3/AN3, 40 PAD11/KWAD11/AN11/ACMPM/AMP0, 41 PAD4/KWAD4/AN4, 42 PAD12/KWAD12/AN12, 43 PAD5/KWAD5/AN5, 44 PAD13/KWAD13/AN13/AMPM0, 45 PAD6/KWAD6/AN6, 46 PAD14/KWAD14/AN14/AMPP0, 47 PAD7/KWAD7/AN7, 48 PAD15/KWAD15/AN15/DACU0, 49 VRH, 50 VDDA, 51 VSSA, 52 PS0/RXD0, 53 PS1/TXD0, 54 PS2/RXD1, 55 PS3/TXD1, 56 PS4/MISO0, 57 PS5/MOSI0, 58 PS6/SCK0, 59 PS7/API_EXTCLK/ECLK/~{SS0}, 60 PM0/RXCAN, 61 PM1/TXCAN, 62 PM2/RXD2, 63 PM3/TXD2, 64 PJ7/KWJ7/~{SS2}

## MC9S12X
designator U?
飞思卡尔单片机
footprint LQFP112
pins: 1 PP3, 2 PP2, 3 PWM1/PP1, 4 PWM0/PP0, 5 PK3, 6 PK2, 7 PK1, 8 PK0, 9 PT0, 10 PT1, 11 PT2, 12 PT3, 13 VDDF, 14 VSS1, 15 PT4, 16 PT5, 17 PT6, 18 PT7, 19 PK5, 20 PK4, 21 PJ1, 22 PJ0, 23 MODC, 24 PB0, 25 PB1, 26 PB2, 27 PB3, 28 PB4, 29 PB5, 30 PB6, 31 PB7, 32 PH7, 33 PH6, 34 PH5, 35 PH4, 36 PE7, 37 PE6, 38 PE5, 39 PE4, 40 VSSX2, 41 VDDX2, 42 ~{RESET}, 43 VDDR, 44 VSS3, 45 VSSPLL, 46 EXTAL, 47 XTAL, 48 VDDPLL, 49 PH3, 50 PH2, 51 PH1, 52 PH0, 53 PE3, 54 PE2, 55 PE1/IRQ, 56 PE0/XIRQ, 57 PA0, 58 PA1, 59 PA2, 60 PA3, 61 PA4, 62 PA5, 63 PA6, 64 PA7, 65 VDD, 66 VSS2, 67 AN00, 68 AN08, 69 AN01, 70 AN09, 71 AN02, 72 AN10, 73 AN03, 74 AN11, 75 AN04, 76 AN12, 77 AN05, 78 AN13, 79 AN06, 80 AN14, 81 AN07, 82 AN15, 83 VDDA1, 84 VRH, 85 VRL, 86 VSSA1, 87 PM7, 88 PM6, 89 PS0, 90 PS1, 91 PS2, 92 PS3, 93 PS4, 94 PS5, 95 PS6, 96 PS7, 97 TEST, 98 PJ7, 99 PJ6, 100 PM5, 101 PM4, 102 PM3/TXCAN1, 103 PM2/RXCAN1, 104 PM1/TXCAN0, 105 PM0/RXCAN0, 106 VSSX1, 107 VDDX1, 108 PK7, 109 PP7, 110 PP6, 111 PP5, 112 PP4

## MC33789
designator U?
飞思卡尔传感器
footprint LQFP-64_EP (LQFP64)
pins: 1 ASST, 2 ~{CS_A}, 3 ~{CS_B}, 4 ~{CS_C}, 5 SCRAP, 6 PSI5_1, 7 PSI5_2, 8 PSI5_3, 9 PSI5_4, 10 GND_PSI, 11 SO, 12 SI, 13 SCK, 14 CLK, 15 ~{CS}, 16 SYNC, 17 OUT2_D, 18 OUT2_S, 19 PPT, 20 OUT1_S, 21 OUT1_D, 22 LIN_ISO, 23 GND_LIN, 24 IN9, 25 IN8, 26 IN7, 27 IN6, 28 IN5, 29 IN4, 30 IN3, 31 IN2, 32 IN1, 33 A_SENSOR, 34 TXD, 35 RXD, 36 AOUT, 37 ~{RST}, 38 ARM, 39 ~{DISARM}, 40 VCCDRI, 41 GNDA, 42 VCC, 43 VSS, 44 VDD, 45 BSTCOMP2, 46 BSTCOMP1, 47 BUCKCOMP2, 48 BUCKCOMP1, 49 VERDIAG, 50 BUCK_GND, 51 BUCK_SW, 52 VBST, 53 ERSW, 54 BST_GND, 55 BST_SW, 56 VER, 57 WAKE, 58 VPWR, 59 VSYNC, 60 CPC2, 61 CPC1, 62 CPGND, 63 VBUCK_R, 64 VBUCK, 65

## Mic2
designator MK?
Microphone
footprint PIN2 (Photosensitive Diode; 2 Leads)
pins: 1, 2

## MOSFET-N
designator Q?
N-Channel MOSFET; PackageDocument: 1995/1996
footprint TO-220AB (TO, Thru-Hole, Vertical, Heatsink Mounted; 3 In-Line Leads; Pitch 2.54 mm)
pins: D, G, S

## MOSFET-P
designator Q?  (value not drawn)
P-Channel MOSFET; PackageDocument: 1995/1996
footprint TO-220AB (TO, Thru-Hole, Vertical, Heatsink Mounted; 3 In-Line Leads; Pitch 2.54 mm)
pins: D, G, S

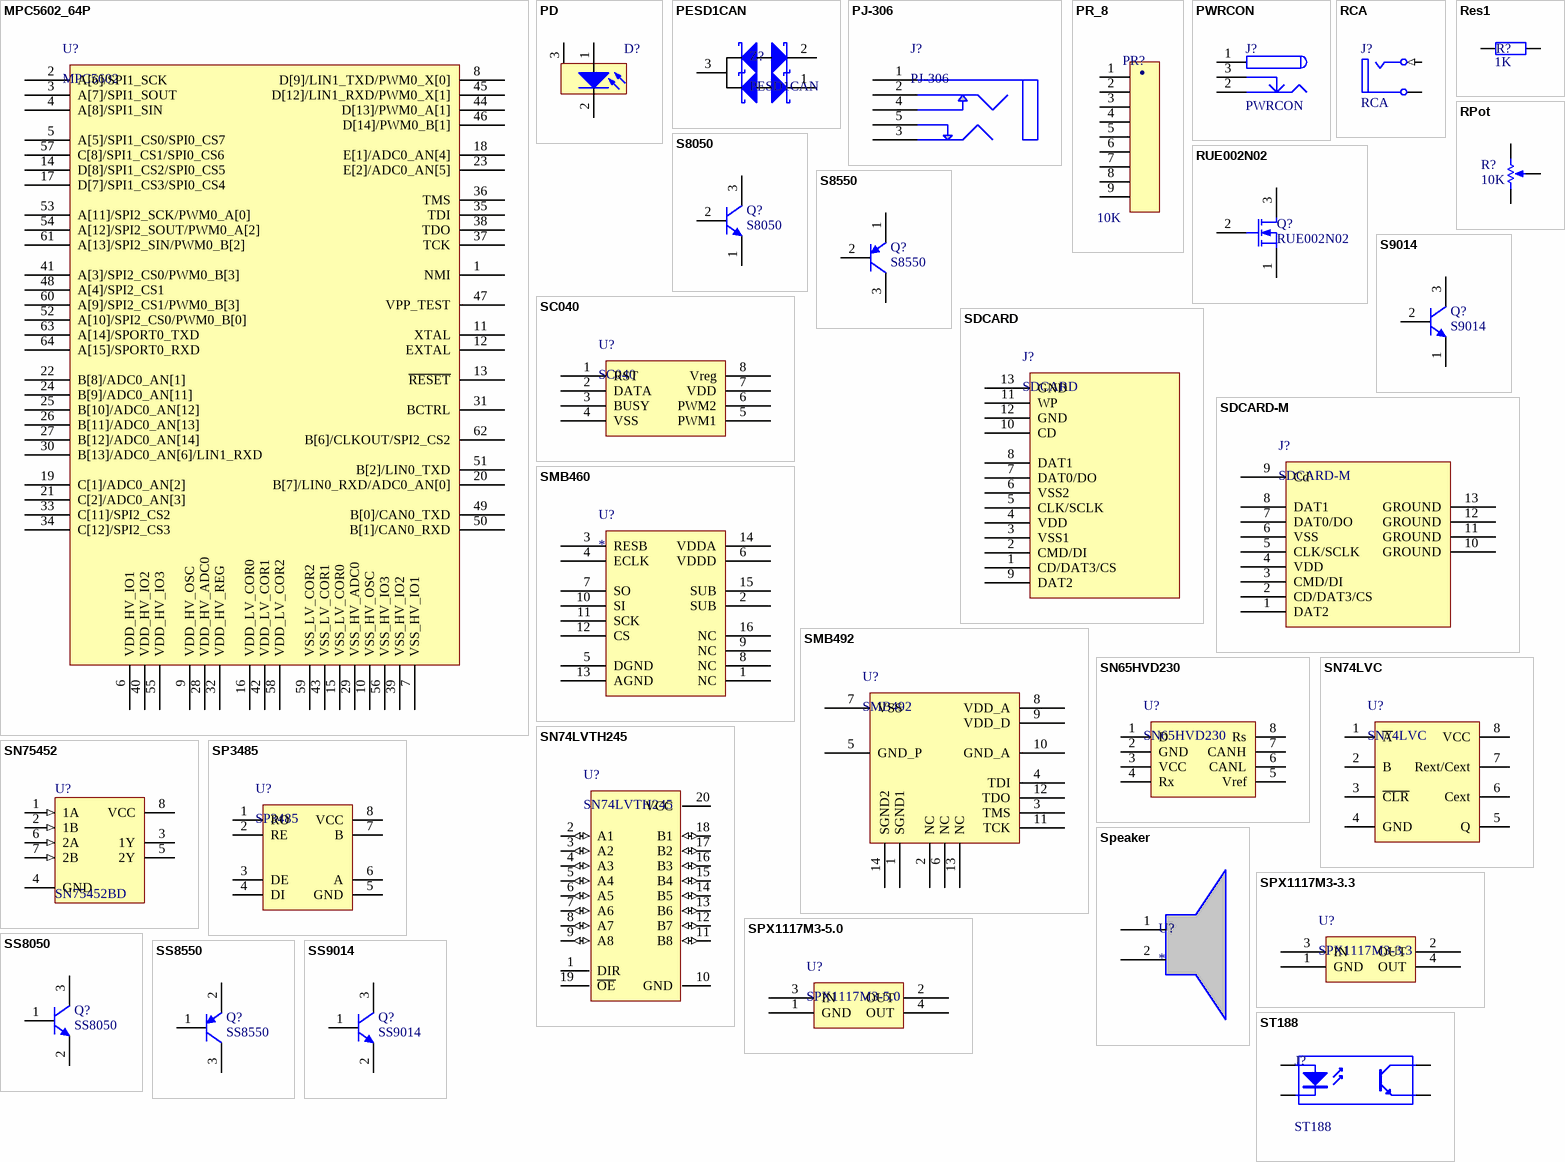
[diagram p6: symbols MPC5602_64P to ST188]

## MPC5602_64P
designator U?, comment MPC5602
Freescale PowerPC
footprint LQFP-64 (LQFP64)
pins: 1 NMI, 2 A[6]/SPI1_SCK, 3 A[7]/SPI1_SOUT, 4 A[8]/SPI1_SIN, 5 A[5]/SPI1_CS0/SPI0_CS7, 6 VDD_HV_IO1, 7 VSS_HV_IO1, 8 D[9]/LIN1_TXD/PWM0_X[0], 9 VDD_HV_OSC, 10 VSS_HV_OSC, 11 XTAL, 12 EXTAL, 13 ~{RESET}, 14 D[8]/SPI1_CS2/SPI0_CS5, 15 VSS_LV_COR0, 16 VDD_LV_COR0, 17 D[7]/SPI1_CS3/SPI0_CS4, 18 E[1]/ADC0_AN[4], 19 C[1]/ADC0_AN[2], 20 B[7]/LIN0_RXD/ADC0_AN[0], 21 C[2]/ADC0_AN[3], 22 B[8]/ADC0_AN[1], 23 E[2]/ADC0_AN[5], 24 B[9]/ADC0_AN[11], 25 B[10]/ADC0_AN[12], 26 B[11]/ADC0_AN[13], 27 B[12]/ADC0_AN[14], 28 VDD_HV_ADC0, 29 VSS_HV_ADC0, 30 B[13]/ADC0_AN[6]/LIN1_RXD, 31 BCTRL, 32 VDD_HV_REG, 33 C[11]/SPI2_CS2, 34 C[12]/SPI2_CS3, 35 TDI, 36 TMS, 37 TCK, 38 TDO, 39 VSS_HV_IO2, 40 VDD_HV_IO2, 41 A[3]/SPI2_CS0/PWM0_B[3], 42 VDD_LV_COR1, 43 VSS_LV_COR1, 44 D[13]/PWM0_A[1], 45 D[12]/LIN1_RXD/PWM0_X[1], 46 D[14]/PWM0_B[1], 47 VPP_TEST, 48 A[4]/SPI2_CS1, 49 B[0]/CAN0_TXD, 50 B[1]/CAN0_RXD, 51 B[2]/LIN0_TXD, 52 A[10]/SPI2_CS0/PWM0_B[0], 53 A[11]/SPI2_SCK/PWM0_A[0], 54 A[12]/SPI2_SOUT/PWM0_A[2], 55 VDD_HV_IO3, 56 VSS_HV_IO3, 57 C[8]/SPI1_CS1/SPI0_CS6, 58 VDD_LV_COR2, 59 VSS_LV_COR2, 60 A[9]/SPI2_CS1/PWM0_B[3], 61 A[13]/SPI2_SIN/PWM0_B[2], 62 B[6]/CLKOUT/SPI2_CS2, 63 A[14]/SPORT0_TXD, 64 A[15]/SPORT0_RXD

## PD
designator D?  (value not drawn)
光电二极管
footprint PD
pins: 1 A, 2 K, 3 0

## PESD1CAN
designator Z?
过压保护
footprint SOT-23 (普通?)
pins: 1, 2, 3

## PJ-306
designator J?
立体声耳机插座
footprint PJ-315-B (立体声耳机插座)
footprint PJ-306 (立体声耳机插座)
pins: 1 COM, 2 L, 3 R, 4 L1, 5 R1

## PR_8
designator PR?, comment value 10K  (hidden comment: RES8-SIP9)
8排直播排电阻
footprint HDR9X1_A (2.54mm)
pins: 1 (power), 2 (power), 3 (power), 4 (power), 5 (power), 6 (power), 7 (power), 8 (power), 9 (power)

## PWRCON
designator J?
直流电源端子
footprint DC-005 (DC母座5.5mm)
footprint DC-002 (DC母座3.5mm)
pins: 1 (power), 2 (power), 3 (power)

## RCA
designator J?
RCA Phono Jack; PCB_Layout: Complies with manufacturer's recommendation.; DrillAndSlotSize: Corresponds to nominal value.
footprint RCA/4.5-H2 (Two Conductor Jack (RCA))
footprint RCJ-04X (Two Conductor Jack (RCA))
pins: 1A Ground (power) "Outer Shield (Sleeve)", 2B Signal (in) "Center Pin (Plug Tip)"

## Res1
designator R?  value 1K  (hidden comment: Res1)
贴片电阻
footprint 0805-1 (贴片带丝印)
footprint 0805-2 (贴片无丝印)
footprint 0603-1 (贴片带丝印)
footprint 1210 (贴片元件)
footprint AXIAL-0.8 (Semiconductor Resistor; 2 Leads)
footprint 2010 (贴片电阻)
footprint 0603-2 (贴片无丝印)
footprint 1206
footprint 2512 (保险丝)
footprint 1812 (保险丝)
footprint AXIAL-0.9 (插件电阻)
pins: 1, 2

## RPot
designator R?  value 10K  (hidden comment: RPot)
精密可调电阻; Sim Note: Enter the Resistance value and the set point into parameter fields.; Set Position: 0.5
footprint VR_A1 (Potentiometer; 3 Leads)
footprint VR_A2
footprint VR_B1 (Potentiometer; 3 Leads)
pins: 1 TOP, 2 TAP, 3 BOT
1 alternate drawing of the same symbol

## RUE002N02
designator Q?
低功耗MOSFET
footprint SOT-416
pins: 1 S, 2 G, 3 D

## S8050
designator Q?
NPN三极管
footprint TO-92A (TO, Flat Index; 3 In-Line, Axial Leads; Body Dia. 4.5mm; Leads 0.51 x 0.48 mm (max))
pins: 1 E, 2 B, 3 C

## S8550
designator Q?
PNP三极管
footprint TO-92A (TO, Flat Index; 3 In-Line, Axial Leads; Body Dia. 4.5mm; Leads 0.51 x 0.48 mm (max))
pins: 1 E, 2 B, 3 C

## S9014
designator Q?
NPN三极管
footprint TO-92A (TO, Flat Index; 3 In-Line, Axial Leads; Body Dia. 4.5mm; Leads 0.51 x 0.48 mm (max))
pins: 1 E, 2 B, 3 C

## SC040
designator U?
语音
footprint NSO8_N (SOIC-max660)
pins: 1 RST, 2 DATA, 3 BUSY, 4 VSS, 5 PWM1, 6 PWM2, 7 VDD, 8 Vreg

## SDCARD
designator J?
SD卡自弹
footprint SDCARD_B (SD卡自弹)
pins: 1 CD/DAT3/CS, 2 CMD/DI, 3 VSS1, 4 VDD, 5 CLK/SCLK, 6 VSS2, 7 DAT0/DO, 8 DAT1, 9 DAT2, 10 CD, 11 WP, 12 GND, 13 GND

## SDCARD-M
designator J?
TF卡槽
footprint SDCARD-M (TF卡)
pins: 1 DAT2, 2 CD/DAT3/CS, 3 CMD/DI, 4 VDD, 5 CLK/SCLK, 6 VSS, 7 DAT0/DO, 8 DAT1, 9 Cd, 10 GROUND, 11 GROUND, 12 GROUND, 13 GROUND

## SMB460
designator U?
SMB460
footprint SOIC127P1050X265-16N (SOIC SMB460)
pins: 1 NC, 2 SUB, 3 RESB, 4 ECLK, 5 DGND, 6 VDDD, 7 SO, 8 NC, 9 NC, 10 SI, 11 SCK, 12 CS, 13 AGND, 14 VDDA, 15 SUB, 16 NC

## SMB492
designator U?
外围加速度传感器
footprint SOP-14N (SOP, 14-Leads,)
pins: 1 SGND1, 2 NC, 3 TMS, 4 TDI, 5 GND_P, 6 NC, 7 VSS, 8 VDD_A, 9 VDD_D, 10 GND_A, 11 TCK, 12 TDO, 13 NC, 14 SGND2

## SN65HVD230
designator U?
CANоƬ
footprint NSO8_N (SOIC-max660)
pins: 1 D, 2 GND, 3 VCC, 4 Rx, 5 Vref, 6 CANL, 7 CANH, 8 Rs

## SN74LVC
designator U?
footprint PDSO-G8 (U)
pins: 1 ~{A}, 2 B, 3 ~{CLR}, 4 GND, 5 Q, 6 Cext, 7 Rext/Cext, 8 VCC

## SN74LVTH245
designator U?
双向数据传输
footprint TSSOP20 (Shrink Small Outline; 20 Leads; Body Width 4.4 mm; Pitch 0.65 mm)
pins: 1 DIR, 2 A1 (io), 3 A2 (io), 4 A3 (io), 5 A4 (io), 6 A5 (io), 7 A6 (io), 8 A7 (io), 9 A8 (io), 10 GND, 11 B8 (io), 12 B7 (io), 13 B6 (io), 14 B5 (io), 15 B4 (io), 16 B3 (io), 17 B2 (io), 18 B1 (io), 19 ~{OE}, 20 VCC (power)

## SN75452
designator U?, comment SN75452BD
Dual Peripheral Driver; Package Information: Latest Revision: Jan-1998
footprint NSO8_N (SOIC-max660)
pins: 1 1A (in), 2 1B (in), 3 1Y (oc), 4 GND (power), 5 2Y (oc), 6 2A (in), 7 2B (in), 8 VCC (power)

## SP3485
designator U?
485总线芯片
footprint NSO8_N (SOIC-max660)
pins: 1 RO, 2 RE, 3 DE, 4 DI, 5 GND, 6 A, 7 B, 8 VCC

## Speaker
designator U?
Speaker
pins: 1 0, 2 1

## SPX1117M3-3.3
designator U?
3.3V稳压芯片
footprint SOT-223 (ASM1117 -3.3V)
pins: 1 GND, 2 OUT, 3 IN, 4 OUT

## SPX1117M3-5.0
designator U?
5.0V稳压芯片
footprint SOT-223 (ASM1117 -3.3V)
pins: 1 GND, 2 OUT, 3 IN, 4 OUT

## SS8050
designator Q?
NPN贴片三极管
footprint SOT-23 (普通贴片三极管)
pins: 1 B, 2 E, 3 C

## SS8550
designator Q?
PNP贴片三极管
footprint SOT-23 (普通贴片三极管)
pins: 1 B, 2 E, 3 C

## SS9014
designator Q?
NPN贴片三极管
footprint SOT-23 (普通贴片三极管)
pins: 1 B, 2 E, 3 C

## ST188
designator J?
反射式光电传感器
footprint ST188 (反射光电传感器)
pins: 1 A "Anode", 2 K "Cathode", 3 E "Emitter", 4 C "Collector"

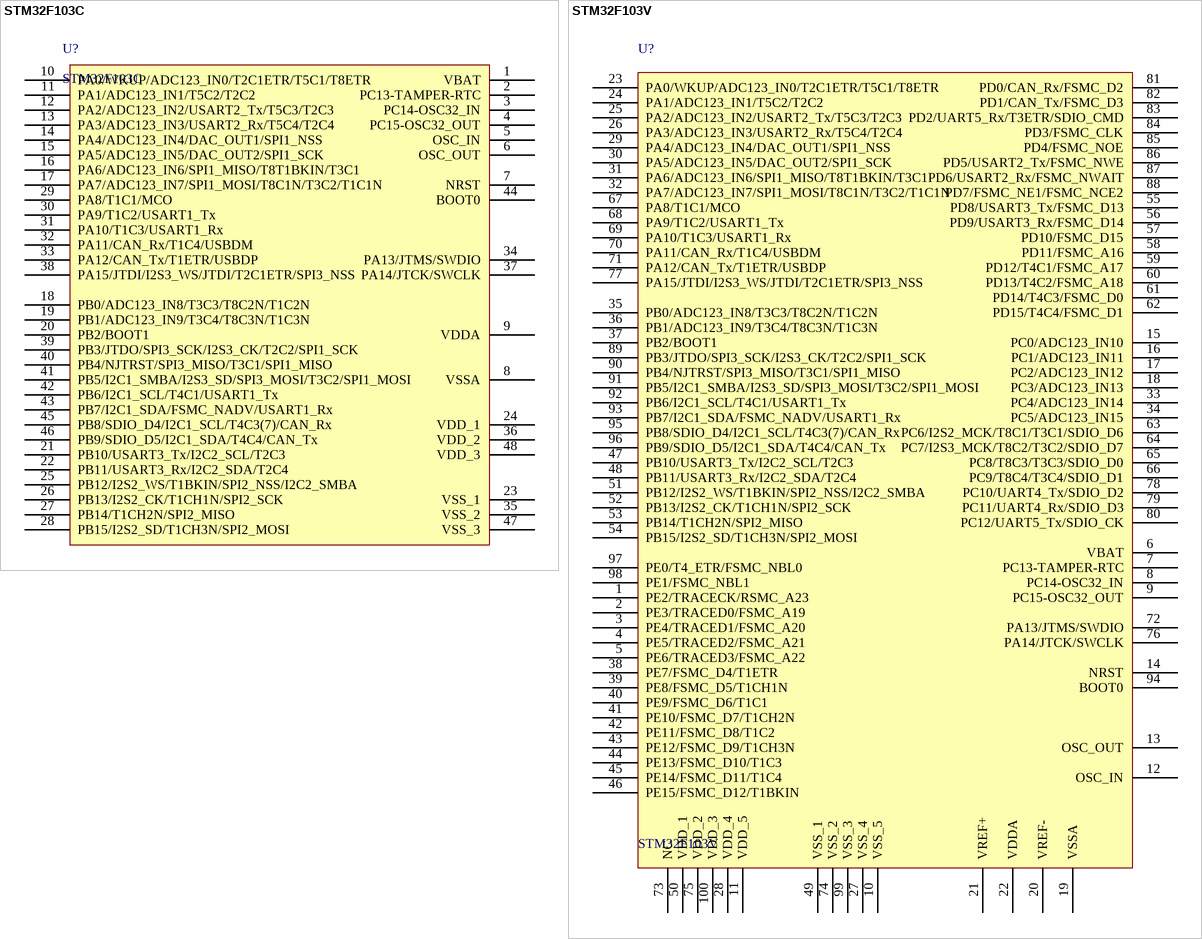
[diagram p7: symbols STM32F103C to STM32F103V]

## STM32F103C
designator U?
STM32单片机48引脚
footprint LQFP-48_M (Thin QFP, 48-Leads, Body 7x7mm, Pitch 0.5mm, IPC Low Density)
pins: 1 VBAT, 2 PC13-TAMPER-RTC, 3 PC14-OSC32_IN, 4 PC15-OSC32_OUT, 5 OSC_IN, 6 OSC_OUT, 7 NRST, 8 VSSA, 9 VDDA, 10 PA0/WKUP/ADC123_IN0/T2C1ETR/T5C1/T8ETR, 11 PA1/ADC123_IN1/T5C2/T2C2, 12 PA2/ADC123_IN2/USART2_Tx/T5C3/T2C3, 13 PA3/ADC123_IN3/USART2_Rx/T5C4/T2C4, 14 PA4/ADC123_IN4/DAC_OUT1/SPI1_NSS, 15 PA5/ADC123_IN5/DAC_OUT2/SPI1_SCK, 16 PA6/ADC123_IN6/SPI1_MISO/T8T1BKIN/T3C1, 17 PA7/ADC123_IN7/SPI1_MOSI/T8C1N/T3C2/T1C1N, 18 PB0/ADC123_IN8/T3C3/T8C2N/T1C2N, 19 PB1/ADC123_IN9/T3C4/T8C3N/T1C3N, 20 PB2/BOOT1, 21 PB10/USART3_Tx/I2C2_SCL/T2C3, 22 PB11/USART3_Rx/I2C2_SDA/T2C4, 23 VSS_1, 24 VDD_1, 25 PB12/I2S2_WS/T1BKIN/SPI2_NSS/I2C2_SMBA, 26 PB13/I2S2_CK/T1CH1N/SPI2_SCK, 27 PB14/T1CH2N/SPI2_MISO, 28 PB15/I2S2_SD/T1CH3N/SPI2_MOSI, 29 PA8/T1C1/MCO, 30 PA9/T1C2/USART1_Tx, 31 PA10/T1C3/USART1_Rx, 32 PA11/CAN_Rx/T1C4/USBDM, 33 PA12/CAN_Tx/T1ETR/USBDP, 34 PA13/JTMS/SWDIO, 35 VSS_2, 36 VDD_2, 37 PA14/JTCK/SWCLK, 38 PA15/JTDI/I2S3_WS/JTDI/T2C1ETR/SPI3_NSS, 39 PB3/JTDO/SPI3_SCK/I2S3_CK/T2C2/SPI1_SCK, 40 PB4/NJTRST/SPI3_MISO/T3C1/SPI1_MISO, 41 PB5/I2C1_SMBA/I2S3_SD/SPI3_MOSI/T3C2/SPI1_MOSI, 42 PB6/I2C1_SCL/T4C1/USART1_Tx, 43 PB7/I2C1_SDA/FSMC_NADV/USART1_Rx, 44 BOOT0, 45 PB8/SDIO_D4/I2C1_SCL/T4C3(7)/CAN_Rx, 46 PB9/SDIO_D5/I2C1_SDA/T4C4/CAN_Tx, 47 VSS_3, 48 VDD_3

## STM32F103V
designator U?
STM32单片机100引脚
footprint LQFP-100_M (Thin QFP, 100)
pins: 1 PE2/TRACECK/RSMC_A23, 2 PE3/TRACED0/FSMC_A19, 3 PE4/TRACED1/FSMC_A20, 4 PE5/TRACED2/FSMC_A21, 5 PE6/TRACED3/FSMC_A22, 6 VBAT, 7 PC13-TAMPER-RTC, 8 PC14-OSC32_IN, 9 PC15-OSC32_OUT, 10 VSS_5, 11 VDD_5, 12 OSC_IN, 13 OSC_OUT, 14 NRST, 15 PC0/ADC123_IN10, 16 PC1/ADC123_IN11, 17 PC2/ADC123_IN12, 18 PC3/ADC123_IN13, 19 VSSA, 20 VREF-, 21 VREF+, 22 VDDA, 23 PA0/WKUP/ADC123_IN0/T2C1ETR/T5C1/T8ETR, 24 PA1/ADC123_IN1/T5C2/T2C2, 25 PA2/ADC123_IN2/USART2_Tx/T5C3/T2C3, 26 PA3/ADC123_IN3/USART2_Rx/T5C4/T2C4, 27 VSS_4, 28 VDD_4, 29 PA4/ADC123_IN4/DAC_OUT1/SPI1_NSS, 30 PA5/ADC123_IN5/DAC_OUT2/SPI1_SCK, 31 PA6/ADC123_IN6/SPI1_MISO/T8T1BKIN/T3C1, 32 PA7/ADC123_IN7/SPI1_MOSI/T8C1N/T3C2/T1C1N, 33 PC4/ADC123_IN14, 34 PC5/ADC123_IN15, 35 PB0/ADC123_IN8/T3C3/T8C2N/T1C2N, 36 PB1/ADC123_IN9/T3C4/T8C3N/T1C3N, 37 PB2/BOOT1, 38 PE7/FSMC_D4/T1ETR, 39 PE8/FSMC_D5/T1CH1N, 40 PE9/FSMC_D6/T1C1, 41 PE10/FSMC_D7/T1CH2N, 42 PE11/FSMC_D8/T1C2, 43 PE12/FSMC_D9/T1CH3N, 44 PE13/FSMC_D10/T1C3, 45 PE14/FSMC_D11/T1C4, 46 PE15/FSMC_D12/T1BKIN, 47 PB10/USART3_Tx/I2C2_SCL/T2C3, 48 PB11/USART3_Rx/I2C2_SDA/T2C4, 49 VSS_1, 50 VDD_1, 51 PB12/I2S2_WS/T1BKIN/SPI2_NSS/I2C2_SMBA, 52 PB13/I2S2_CK/T1CH1N/SPI2_SCK, 53 PB14/T1CH2N/SPI2_MISO, 54 PB15/I2S2_SD/T1CH3N/SPI2_MOSI, 55 PD8/USART3_Tx/FSMC_D13, 56 PD9/USART3_Rx/FSMC_D14, 57 PD10/FSMC_D15, 58 PD11/FSMC_A16, 59 PD12/T4C1/FSMC_A17, 60 PD13/T4C2/FSMC_A18, 61 PD14/T4C3/FSMC_D0, 62 PD15/T4C4/FSMC_D1, 63 PC6/I2S2_MCK/T8C1/T3C1/SDIO_D6, 64 PC7/I2S3_MCK/T8C2/T3C2/SDIO_D7, 65 PC8/T8C3/T3C3/SDIO_D0, 66 PC9/T8C4/T3C4/SDIO_D1, 67 PA8/T1C1/MCO, 68 PA9/T1C2/USART1_Tx, 69 PA10/T1C3/USART1_Rx, 70 PA11/CAN_Rx/T1C4/USBDM, 71 PA12/CAN_Tx/T1ETR/USBDP, 72 PA13/JTMS/SWDIO, 73 NC, 74 VSS_2, 75 VDD_2, 76 PA14/JTCK/SWCLK, 77 PA15/JTDI/I2S3_WS/JTDI/T2C1ETR/SPI3_NSS, 78 PC10/UART4_Tx/SDIO_D2, 79 PC11/UART4_Rx/SDIO_D3, 80 PC12/UART5_Tx/SDIO_CK, 81 PD0/CAN_Rx/FSMC_D2, 82 PD1/CAN_Tx/FSMC_D3, 83 PD2/UART5_Rx/T3ETR/SDIO_CMD, 84 PD3/FSMC_CLK, 85 PD4/FSMC_NOE, 86 PD5/USART2_Tx/FSMC_NWE, 87 PD6/USART2_Rx/FSMC_NWAIT, 88 PD7/FSMC_NE1/FSMC_NCE2, 89 PB3/JTDO/SPI3_SCK/I2S3_CK/T2C2/SPI1_SCK, 90 PB4/NJTRST/SPI3_MISO/T3C1/SPI1_MISO, 91 PB5/I2C1_SMBA/I2S3_SD/SPI3_MOSI/T3C2/SPI1_MOSI, 92 PB6/I2C1_SCL/T4C1/USART1_Tx, 93 PB7/I2C1_SDA/FSMC_NADV/USART1_Rx, 94 BOOT0, 95 PB8/SDIO_D4/I2C1_SCL/T4C3(7)/CAN_Rx, 96 PB9/SDIO_D5/I2C1_SDA/T4C4/CAN_Tx, 97 PE0/T4_ETR/FSMC_NBL0, 98 PE1/FSMC_NBL1, 99 VSS_3, 100 VDD_3

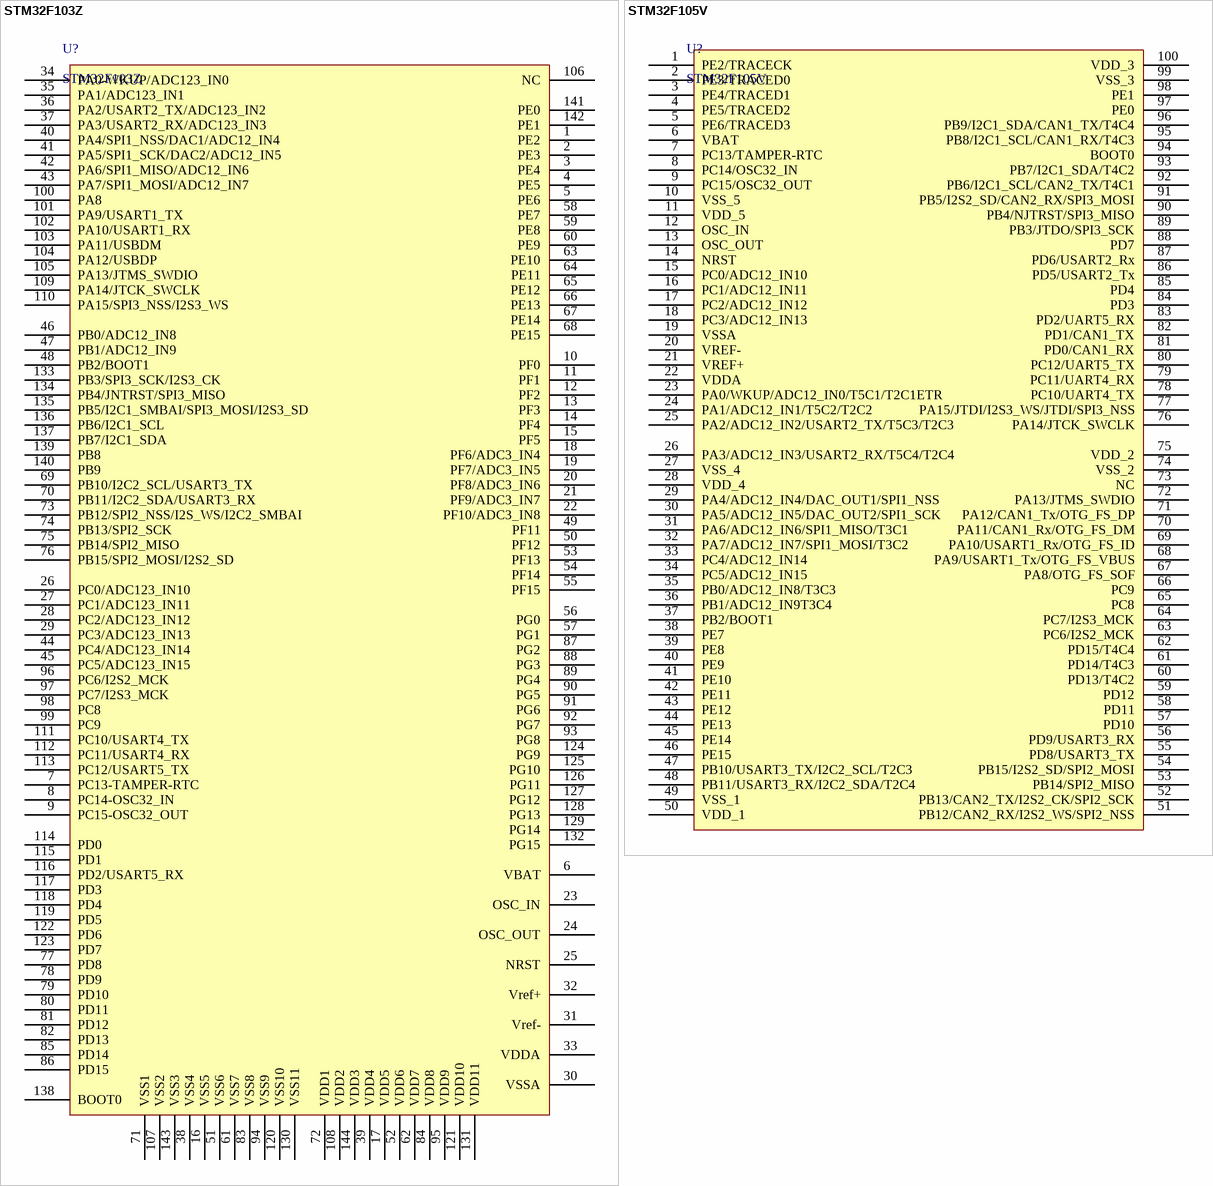
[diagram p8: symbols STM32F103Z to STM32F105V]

## STM32F103Z
designator U?
STM32单片机144引脚
footprint TQFP144_N (Thin QFP, 144-Leads, Body 20x20mm, Pitch 0.5mm, IPC Medium Density)
pins: 1 PE2, 2 PE3, 3 PE4, 4 PE5, 5 PE6, 6 VBAT, 7 PC13-TAMPER-RTC, 8 PC14-OSC32_IN, 9 PC15-OSC32_OUT, 10 PF0, 11 PF1, 12 PF2, 13 PF3, 14 PF4, 15 PF5, 16 VSS5, 17 VDD5, 18 PF6/ADC3_IN4, 19 PF7/ADC3_IN5, 20 PF8/ADC3_IN6, 21 PF9/ADC3_IN7, 22 PF10/ADC3_IN8, 23 OSC_IN, 24 OSC_OUT, 25 NRST, 26 PC0/ADC123_IN10, 27 PC1/ADC123_IN11, 28 PC2/ADC123_IN12, 29 PC3/ADC123_IN13, 30 VSSA, 31 Vref-, 32 Vref+, 33 VDDA, 34 PA0-WKUP/ADC123_IN0, 35 PA1/ADC123_IN1, 36 PA2/USART2_TX/ADC123_IN2, 37 PA3/USART2_RX/ADC123_IN3, 38 VSS4, 39 VDD4, 40 PA4/SPI1_NSS/DAC1/ADC12_IN4, 41 PA5/SPI1_SCK/DAC2/ADC12_IN5, 42 PA6/SPI1_MISO/ADC12_IN6, 43 PA7/SPI1_MOSI/ADC12_IN7, 44 PC4/ADC123_IN14, 45 PC5/ADC123_IN15, 46 PB0/ADC12_IN8, 47 PB1/ADC12_IN9, 48 PB2/BOOT1, 49 PF11, 50 PF12, 51 VSS6, 52 VDD6, 53 PF13, 54 PF14, 55 PF15, 56 PG0, 57 PG1, 58 PE7, 59 PE8, 60 PE9, 61 VSS7, 62 VDD7, 63 PE10, 64 PE11, 65 PE12, 66 PE13, 67 PE14, 68 PE15, 69 PB10/I2C2_SCL/USART3_TX, 70 PB11/I2C2_SDA/USART3_RX, 71 VSS1, 72 VDD1, 73 PB12/SPI2_NSS/I2S_WS/I2C2_SMBAI, 74 PB13/SPI2_SCK, 75 PB14/SPI2_MISO, 76 PB15/SPI2_MOSI/I2S2_SD, 77 PD8, 78 PD9, 79 PD10, 80 PD11, 81 PD12, 82 PD13, 83 VSS8, 84 VDD8, 85 PD14, 86 PD15, 87 PG2, 88 PG3, 89 PG4, 90 PG5, 91 PG6, 92 PG7, 93 PG8, 94 VSS9, 95 VDD9, 96 PC6/I2S2_MCK, 97 PC7/I2S3_MCK, 98 PC8, 99 PC9, 100 PA8, 101 PA9/USART1_TX, 102 PA10/USART1_RX, 103 PA11/USBDM, 104 PA12/USBDP, 105 PA13/JTMS_SWDIO, 106 NC, 107 VSS2, 108 VDD2, 109 PA14/JTCK_SWCLK, 110 PA15/SPI3_NSS/I2S3_WS, 111 PC10/USART4_TX, 112 PC11/USART4_RX, 113 PC12/USART5_TX, 114 PD0, 115 PD1, 116 PD2/USART5_RX, 117 PD3, 118 PD4, 119 PD5, 120 VSS10, 121 VDD10, 122 PD6, 123 PD7, 124 PG9, 125 PG10, 126 PG11, 127 PG12, 128 PG13, 129 PG14, 130 VSS11, 131 VDD11, 132 PG15, 133 PB3/SPI3_SCK/I2S3_CK, 134 PB4/JNTRST/SPI3_MISO, 135 PB5/I2C1_SMBAI/SPI3_MOSI/I2S3_SD, 136 PB6/I2C1_SCL, 137 PB7/I2C1_SDA, 138 BOOT0, 139 PB8, 140 PB9, 141 PE0, 142 PE1, 143 VSS3, 144 VDD3

## STM32F105V
designator U?
STM32单片机100引脚
footprint LQFP-100_M (Thin QFP, 100)
pins: 1 PE2/TRACECK, 2 PE3/TRACED0, 3 PE4/TRACED1, 4 PE5/TRACED2, 5 PE6/TRACED3, 6 VBAT, 7 PC13/TAMPER-RTC, 8 PC14/OSC32_IN, 9 PC15/OSC32_OUT, 10 VSS_5, 11 VDD_5, 12 OSC_IN, 13 OSC_OUT, 14 NRST, 15 PC0/ADC12_IN10, 16 PC1/ADC12_IN11, 17 PC2/ADC12_IN12, 18 PC3/ADC12_IN13, 19 VSSA, 20 VREF-, 21 VREF+, 22 VDDA, 23 PA0/WKUP/ADC12_IN0/T5C1/T2C1ETR, 24 PA1/ADC12_IN1/T5C2/T2C2, 25 PA2/ADC12_IN2/USART2_TX/T5C3/T2C3, 26 PA3/ADC12_IN3/USART2_RX/T5C4/T2C4, 27 VSS_4, 28 VDD_4, 29 PA4/ADC12_IN4/DAC_OUT1/SPI1_NSS, 30 PA5/ADC12_IN5/DAC_OUT2/SPI1_SCK, 31 PA6/ADC12_IN6/SPI1_MISO/T3C1, 32 PA7/ADC12_IN7/SPI1_MOSI/T3C2, 33 PC4/ADC12_IN14, 34 PC5/ADC12_IN15, 35 PB0/ADC12_IN8/T3C3, 36 PB1/ADC12_IN9T3C4, 37 PB2/BOOT1, 38 PE7, 39 PE8, 40 PE9, 41 PE10, 42 PE11, 43 PE12, 44 PE13, 45 PE14, 46 PE15, 47 PB10/USART3_TX/I2C2_SCL/T2C3, 48 PB11/USART3_RX/I2C2_SDA/T2C4, 49 VSS_1, 50 VDD_1, 51 PB12/CAN2_RX/I2S2_WS/SPI2_NSS, 52 PB13/CAN2_TX/I2S2_CK/SPI2_SCK, 53 PB14/SPI2_MISO, 54 PB15/I2S2_SD/SPI2_MOSI, 55 PD8/USART3_TX, 56 PD9/USART3_RX, 57 PD10, 58 PD11, 59 PD12, 60 PD13/T4C2, 61 PD14/T4C3, 62 PD15/T4C4, 63 PC6/I2S2_MCK, 64 PC7/I2S3_MCK, 65 PC8, 66 PC9, 67 PA8/OTG_FS_SOF, 68 PA9/USART1_Tx/OTG_FS_VBUS, 69 PA10/USART1_Rx/OTG_FS_ID, 70 PA11/CAN1_Rx/OTG_FS_DM, 71 PA12/CAN1_Tx/OTG_FS_DP, 72 PA13/JTMS_SWDIO, 73 NC, 74 VSS_2, 75 VDD_2, 76 PA14/JTCK_SWCLK, 77 PA15/JTDI/I2S3_WS/JTDI/SPI3_NSS, 78 PC10/UART4_TX, 79 PC11/UART4_RX, 80 PC12/UART5_TX, 81 PD0/CAN1_RX, 82 PD1/CAN1_TX, 83 PD2/UART5_RX, 84 PD3, 85 PD4, 86 PD5/USART2_Tx, 87 PD6/USART2_Rx, 88 PD7, 89 PB3/JTDO/SPI3_SCK, 90 PB4/NJTRST/SPI3_MISO, 91 PB5/I2S2_SD/CAN2_RX/SPI3_MOSI, 92 PB6/I2C1_SCL/CAN2_TX/T4C1, 93 PB7/I2C1_SDA/T4C2, 94 BOOT0, 95 PB8/I2C1_SCL/CAN1_RX/T4C3, 96 PB9/I2C1_SDA/CAN1_TX/T4C4, 97 PE0, 98 PE1, 99 VSS_3, 100 VDD_3

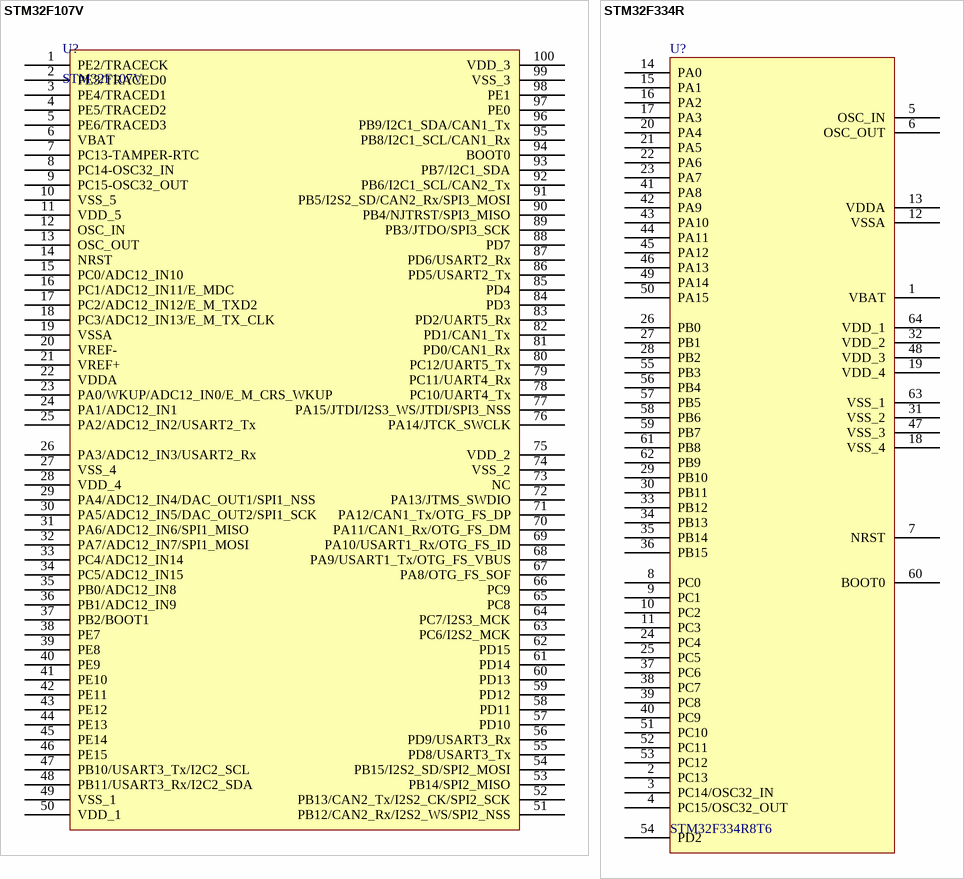
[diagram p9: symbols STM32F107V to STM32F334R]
